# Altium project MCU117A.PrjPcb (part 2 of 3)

## Sheet MCU117A_EtherCAT.SchDoc
size 431 x 279 mm; Date: Not shown in title block; ApprovedBy: Not shown in title block; CheckedBy: Not shown in title block; Author: Not shown in title block; CompanyName: Not shown in title block; Engineer: Not shown in title block; Organization: Not shown in title block; Address1: Not shown in title block; Address2: Not shown in title block; Address3: Not shown in title block; Address4: Not shown in title block; DocumentNumber: 6; Revision: Use project parameter SCH_Rev; SheetNumber: 6; SheetTotal: 9; PageSetup: Record=PageOptions¦CenterHorizontal=True¦CenterVertical=True¦PrintScale=1.00¦XCorrection=1.00¦YCorrection=1.00¦PrintKind=0¦BorderSize=5000000¦LeftOffset=0¦BottomOffset=0¦Orientation=2¦PaperLength=1000¦PaperWidth=1000¦Scale=100¦PaperSource=15¦PrintQuality=600¦MediaType=1¦DitherType=10¦PaperKind=Letter¦PrintScaleMode=1
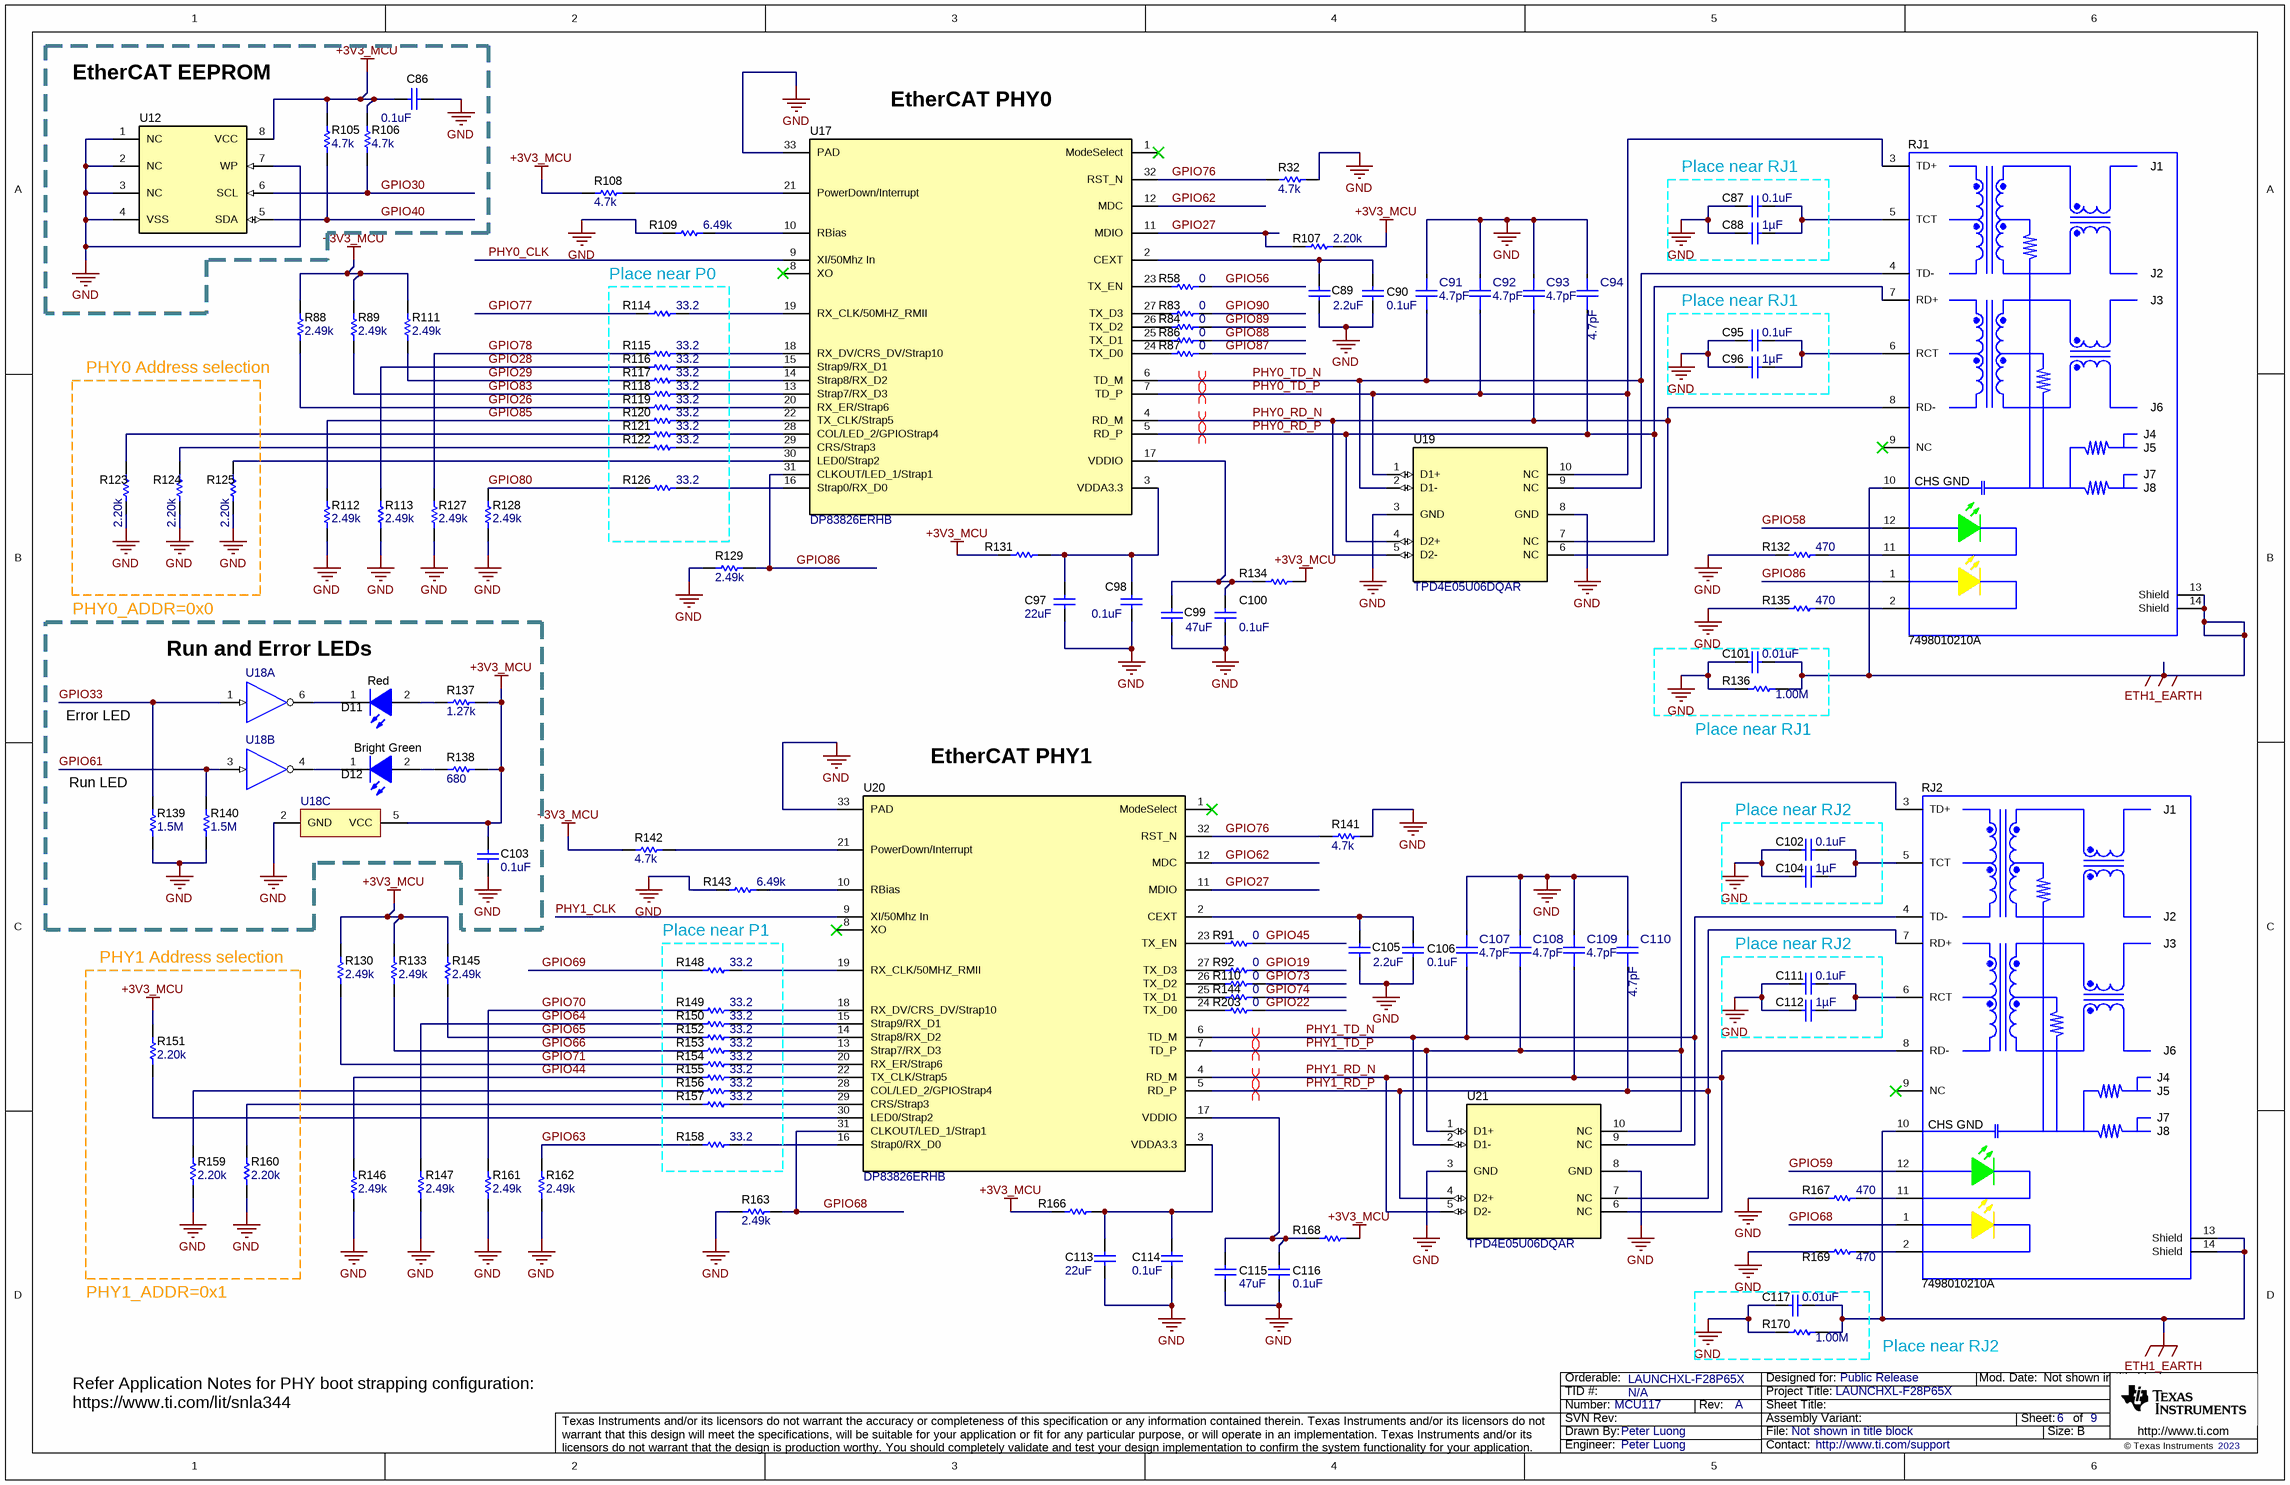
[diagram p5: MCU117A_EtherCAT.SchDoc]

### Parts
C86  ValueDisplayed: 0.1uF  [0402]  (hidden comment: 885012205037)
C87  ValueDisplayed: 0.1uF  [0402]  (hidden comment: CGA2B3X7R1H104K050BB)
C88  ValueDisplayed: 1µF  [0402]  (hidden comment: GRM155R61E105KE11D)
C89  ValueDisplayed: 2.2uF  [0402_065]  (hidden comment: C1005X5R1V225K050BC)
C90  ValueDisplayed: 0.1uF  [0402]  (hidden comment: 885012205037)
C91  ValueDisplayed: 4.7pF  [FP-885012005053_0402-MFG]  (hidden comment: 885012005053)
C92  ValueDisplayed: 4.7pF  [FP-885012005053_0402-MFG]  (hidden comment: 885012005053)
C93  ValueDisplayed: 4.7pF  [FP-885012005053_0402-MFG]  (hidden comment: 885012005053)
C94  ValueDisplayed: 4.7pF  [FP-885012005053_0402-MFG]  (hidden comment: 885012005053)
C95  ValueDisplayed: 0.1uF  [0402]  (hidden comment: CGA2B3X7R1H104K050BB)
C96  ValueDisplayed: 1µF  [0402]  (hidden comment: GRM155R61E105KE11D)
C97  ValueDisplayed: 22uF  [0603]  (hidden comment: GRM188R61A226ME15D)
C98  ValueDisplayed: 0.1uF  [0402]  (hidden comment: 885012205037)
C99  ValueDisplayed: 47uF  [0603]  (hidden comment: GRM188R60J476ME15D)
C100  ValueDisplayed: 0.1uF  [0402]  (hidden comment: 885012205037)
C101  ValueDisplayed: 0.01uF  [0402]  (hidden comment: GRM155R71H103KA88D)
C102  ValueDisplayed: 0.1uF  [0402]  (hidden comment: CGA2B3X7R1H104K050BB)
C103  ValueDisplayed: 0.1uF  [0402]  (hidden comment: 885012205037)
C104  ValueDisplayed: 1µF  [0402]  (hidden comment: GRM155R61E105KE11D)
C105  ValueDisplayed: 2.2uF  [0402_065]  (hidden comment: C1005X5R1V225K050BC)
C106  ValueDisplayed: 0.1uF  [0402]  (hidden comment: 885012205037)
C107  ValueDisplayed: 4.7pF  [FP-885012005053_0402-MFG]  (hidden comment: 885012005053)
C108  ValueDisplayed: 4.7pF  [FP-885012005053_0402-MFG]  (hidden comment: 885012005053)
C109  ValueDisplayed: 4.7pF  [FP-885012005053_0402-MFG]  (hidden comment: 885012005053)
C110  ValueDisplayed: 4.7pF  [FP-885012005053_0402-MFG]  (hidden comment: 885012005053)
C111  ValueDisplayed: 0.1uF  [0402]  (hidden comment: CGA2B3X7R1H104K050BB)
C112  ValueDisplayed: 1µF  [0402]  (hidden comment: GRM155R61E105KE11D)
C113  ValueDisplayed: 22uF  [0603]  (hidden comment: GRM188R61A226ME15D)
C114  ValueDisplayed: 0.1uF  [0402]  (hidden comment: 885012205037)
C115  ValueDisplayed: 47uF  [0603]  (hidden comment: GRM188R60J476ME15D)
C116  ValueDisplayed: 0.1uF  [0402]  (hidden comment: 885012205037)
C117  ValueDisplayed: 0.01uF  [0402]  (hidden comment: GRM155R71H103KA88D)
D11  value Red  [WL-SMCW_RED_0805]  (hidden comment: 150080SS75000)
D12  value Bright Green  [WL-SMCW_Green_0805]  (hidden comment: 150080VS75000)
R32  ValueDisplayed: 4.7k  [0402]  (hidden comment: CRCW04024K70JNED)
R58  ValueDisplayed: 0  [0402]  (hidden comment: CRCW04020000Z0EDHP)
R83  ValueDisplayed: 0  [0402]  (hidden comment: CRCW04020000Z0EDHP)
R84  ValueDisplayed: 0  [0402]  (hidden comment: CRCW04020000Z0EDHP)
R86  ValueDisplayed: 0  [0402]  (hidden comment: CRCW04020000Z0EDHP)
R87  ValueDisplayed: 0  [0402]  (hidden comment: CRCW04020000Z0EDHP)
R88  ValueDisplayed: 2.49k  [0402]  (hidden comment: CRCW04022K49FKED)
R89  ValueDisplayed: 2.49k  [0402]  (hidden comment: CRCW04022K49FKED)
R91  ValueDisplayed: 0  [0402]  (hidden comment: CRCW04020000Z0EDHP)
R92  ValueDisplayed: 0  [0402]  (hidden comment: CRCW04020000Z0EDHP)
R105  ValueDisplayed: 4.7k  [0402]  (hidden comment: CRCW04024K70JNED)
R106  ValueDisplayed: 4.7k  [0402]  (hidden comment: CRCW04024K70JNED)
R107  ValueDisplayed: 2.20k  [0402]  (hidden comment: CRCW04022K20FKED)
R108  ValueDisplayed: 4.7k  [0402]  (hidden comment: CRCW04024K70JNED)
R109  ValueDisplayed: 6.49k  [0402]  (hidden comment: CRCW04026K49FKED)
R110  ValueDisplayed: 0  [0402]  (hidden comment: CRCW04020000Z0EDHP)
R111  ValueDisplayed: 2.49k  [0402]  (hidden comment: CRCW04022K49FKED)
R112  ValueDisplayed: 2.49k  [0402]  (hidden comment: CRCW04022K49FKED)
R113  ValueDisplayed: 2.49k  [0402]  (hidden comment: CRCW04022K49FKED)
R114  ValueDisplayed: 33.2  [0402]  (hidden comment: CRCW040233R2FKED)
R115  ValueDisplayed: 33.2  [0402]  (hidden comment: CRCW040233R2FKED)
R116  ValueDisplayed: 33.2  [0402]  (hidden comment: CRCW040233R2FKED)
R117  ValueDisplayed: 33.2  [0402]  (hidden comment: CRCW040233R2FKED)
R118  ValueDisplayed: 33.2  [0402]  (hidden comment: CRCW040233R2FKED)
R119  ValueDisplayed: 33.2  [0402]  (hidden comment: CRCW040233R2FKED)
R120  ValueDisplayed: 33.2  [0402]  (hidden comment: CRCW040233R2FKED)
R121  ValueDisplayed: 33.2  [0402]  (hidden comment: CRCW040233R2FKED)
R122  ValueDisplayed: 33.2  [0402]  (hidden comment: CRCW040233R2FKED)
R123  ValueDisplayed: 2.20k  [0402]  (hidden comment: CRCW04022K20FKED)
R124  ValueDisplayed: 2.20k  [0402]  (hidden comment: CRCW04022K20FKED)
R125  ValueDisplayed: 2.20k  [0402]  (hidden comment: CRCW04022K20FKED)
R126  ValueDisplayed: 33.2  [0402]  (hidden comment: CRCW040233R2FKED)
R127  ValueDisplayed: 2.49k  [0402]  (hidden comment: CRCW04022K49FKED)
R128  ValueDisplayed: 2.49k  [0402]  (hidden comment: CRCW04022K49FKED)
R129  ValueDisplayed: 2.49k  [0402]  (hidden comment: CRCW04022K49FKED)
R130  ValueDisplayed: 2.49k  [0402]  (hidden comment: CRCW04022K49FKED)
R131  RMCF0402ZT0R00  [FP-RMCF0402ZT0R00_0402 (1005 metric)-0]  (value not drawn)
R132  ValueDisplayed: 470  [0603]  (hidden comment: CRCW0603470RJNEA)
R133  ValueDisplayed: 2.49k  [0402]  (hidden comment: CRCW04022K49FKED)
R134  RMCF0402ZT0R00  [FP-RMCF0402ZT0R00_0402 (1005 metric)-0]  (value not drawn)
R135  ValueDisplayed: 470  [0603]  (hidden comment: CRCW0603470RJNEA)
R136  ValueDisplayed: 1.00M  [0402]  (hidden comment: RMCF0402FT1M00)
R137  ValueDisplayed: 1.27k  [0402]  (hidden comment: CRCW04021K27FKED)
R138  ValueDisplayed: 680  [0402]  (hidden comment: CRCW0402680RJNED)
R139  ValueDisplayed: 1.5M  [0402]  (hidden comment: CRCW04021M50JNED)
R140  ValueDisplayed: 1.5M  [0402]  (hidden comment: CRCW04021M50JNED)
R141  ValueDisplayed: 4.7k  [0402]  (hidden comment: CRCW04024K70JNED)
R142  ValueDisplayed: 4.7k  [0402]  (hidden comment: CRCW04024K70JNED)
R143  ValueDisplayed: 6.49k  [0402]  (hidden comment: CRCW04026K49FKED)
R144  ValueDisplayed: 0  [0402]  (hidden comment: CRCW04020000Z0EDHP)
R145  ValueDisplayed: 2.49k  [0402]  (hidden comment: CRCW04022K49FKED)
R146  ValueDisplayed: 2.49k  [0402]  (hidden comment: CRCW04022K49FKED)
R147  ValueDisplayed: 2.49k  [0402]  (hidden comment: CRCW04022K49FKED)
R148  ValueDisplayed: 33.2  [0402]  (hidden comment: CRCW040233R2FKED)
R149  ValueDisplayed: 33.2  [0402]  (hidden comment: CRCW040233R2FKED)
R150  ValueDisplayed: 33.2  [0402]  (hidden comment: CRCW040233R2FKED)
R151  ValueDisplayed: 2.20k  [0402]  (hidden comment: CRCW04022K20FKED)
R152  ValueDisplayed: 33.2  [0402]  (hidden comment: CRCW040233R2FKED)
R153  ValueDisplayed: 33.2  [0402]  (hidden comment: CRCW040233R2FKED)
R154  ValueDisplayed: 33.2  [0402]  (hidden comment: CRCW040233R2FKED)
R155  ValueDisplayed: 33.2  [0402]  (hidden comment: CRCW040233R2FKED)
R156  ValueDisplayed: 33.2  [0402]  (hidden comment: CRCW040233R2FKED)
R157  ValueDisplayed: 33.2  [0402]  (hidden comment: CRCW040233R2FKED)
R158  ValueDisplayed: 33.2  [0402]  (hidden comment: CRCW040233R2FKED)
R159  ValueDisplayed: 2.20k  [0402]  (hidden comment: CRCW04022K20FKED)
R160  ValueDisplayed: 2.20k  [0402]  (hidden comment: CRCW04022K20FKED)
R161  ValueDisplayed: 2.49k  [0402]  (hidden comment: CRCW04022K49FKED)
R162  ValueDisplayed: 2.49k  [0402]  (hidden comment: CRCW04022K49FKED)
R163  ValueDisplayed: 2.49k  [0402]  (hidden comment: CRCW04022K49FKED)
R166  RMCF0402ZT0R00  [FP-RMCF0402ZT0R00_0402 (1005 metric)-0]  (value not drawn)
R167  ValueDisplayed: 470  [0603]  (hidden comment: CRCW0603470RJNEA)
R168  RMCF0402ZT0R00  [FP-RMCF0402ZT0R00_0402 (1005 metric)-0]  (value not drawn)
R169  ValueDisplayed: 470  [0603]  (hidden comment: CRCW0603470RJNEA)
R170  ValueDisplayed: 1.00M  [0402]  (hidden comment: RMCF0402FT1M00)
R203  ValueDisplayed: 0  [0402]  (hidden comment: CRCW04020000Z0EDHP)
RJ1  7498010210A  [Wurth_7498010210A]
RJ2  7498010210A  [Wurth_7498010210A]
U12  CAT24C16WI-GT3  [SOIC-8]  (value not drawn)
U17  DP83826ERHB  [RHB0032M]
U18  SN74LVC2G06DBVR  [DBV0006A_N]  (value not drawn)  (parts A,B,C of 3)
U19  TPD4E05U06DQAR  [DQA0010A]
U20  DP83826ERHB  [RHB0032M]
U21  TPD4E05U06DQAR  [DQA0010A]

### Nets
+3V3_MCU: C86.2 C103.1 R88.2 R89.2 R105.2 R106.2 R107.2 R108.2 R111.2 R130.2 R131.1 R133.2 R134.2 R137.2 R138.1 R142.2 R145.2 R151.2 R166.1 R168.2 U12.8(VCC) U18.5(VCC)
ETH1_EARTH: C101.2 C117.2 R136.2 R170.2 RJ1.10(CHS_GND) RJ1.13(Shield) RJ1.14(Shield) RJ2.10(CHS_GND) RJ2.13(Shield) RJ2.14(Shield)
GND: C86.1 C87.1 C88.1 C89.2 C90.2 C91.2 C92.2 C93.2 C94.2 C95.1 C96.1 C97.2 C98.2 C99.2 C100.2 C101.1 C102.1 C103.2 C104.1 C105.2 C106.2 C107.2 C108.2 C109.2 C110.2 C111.1 C112.1 C113.2 C114.1 C115.2 C116.1 C117.1 R32.1 R109.1 R112.1 R113.1 R123.1 R124.1 R125.1 R127.1 R128.1 R129.1 R132.1 R135.1 R136.1 R139.2 R140.2 R141.1 R143.1 R146.1 R147.1 R159.1 R160.1 R161.1 R162.1 R163.2 R167.1 R169.1 R170.1 U12.1(NC) U12.2(NC) U12.3(NC) U12.4(VSS) U12.7(WP) U17.33(PAD) U18.2(GND) U19.3(GND) U19.8(GND) U20.33(PAD) U21.3(GND) U21.8(GND)
GPIO19: R92.2
GPIO22: R203.2
GPIO26: R88.1 R119.1
GPIO27: R107.1 U17.11(MDIO) U20.11(MDIO)
GPIO28: R113.2 R116.1
GPIO29: R111.1 R117.1
GPIO30: R106.1 U12.6(SCL)
GPIO33: R139.1 U18.1(1A)
GPIO40: R105.1 U12.5(SDA)
GPIO44: R146.2 R155.1
GPIO45: R91.2
GPIO56: R58.2
GPIO58: RJ1.12(LEFT_LED_ANODE)
GPIO59: RJ2.12(LEFT_LED_ANODE)
GPIO61: R140.1 U18.3(2A)
GPIO62: U17.12(MDC) U20.12(MDC)
GPIO63: R158.1 R162.2
GPIO64: R147.2 R150.1
GPIO65: R145.1 R152.1
GPIO66: R133.1 R153.1
GPIO68: R163.1 RJ2.1(RIGHT_LED_ANODE) U20.31(CLKOUT/LED_1/Strap1)
GPIO69: R148.1
GPIO70: R149.1 R161.2
GPIO71: R130.1 R154.1
GPIO73: R110.2
GPIO74: R144.2
GPIO76: R32.2 R141.2 U17.32(RST_N) U20.32(RST_N)
GPIO77: R114.1
GPIO78: R115.1 R127.2
GPIO80: R126.1 R128.2
GPIO83: R89.1 R118.1
GPIO85: R112.2 R120.1
GPIO86: R129.2 RJ1.1(RIGHT_LED_ANODE) U17.31(CLKOUT/LED_1/Strap1)
GPIO87: R87.2
GPIO88: R86.2
GPIO89: R84.2
GPIO90: R83.2
PHY0_CLK: U17.9(XI/50Mhz_In)
PHY0_RD_N: C93.1 RJ1.8(RD-) U17.4(RD_M) U19.5(D2-) U19.6(NC)
PHY0_RD_P: C94.1 RJ1.7(RD+) U17.5(RD_P) U19.4(D2+) U19.7(NC)
PHY0_TD_N: C91.1 RJ1.4(TD-) U17.6(TD_M) U19.2(D1-) U19.9(NC)
PHY0_TD_P: C92.1 RJ1.3(TD+) U17.7(TD_P) U19.1(D1+) U19.10(NC)
PHY1_CLK: U20.9(XI/50Mhz_In)
PHY1_RD_N: C109.1 RJ2.8(RD-) U20.4(RD_M) U21.5(D2-) U21.6(NC)
PHY1_RD_P: C110.1 RJ2.7(RD+) U20.5(RD_P) U21.4(D2+) U21.7(NC)
PHY1_TD_N: C107.1 RJ2.4(TD-) U20.6(TD_M) U21.2(D1-) U21.9(NC)
PHY1_TD_P: C108.1 RJ2.3(TD+) U20.7(TD_P) U21.1(D1+) U21.10(NC)
NetC87_2: C87.2 C88.2 RJ1.5(TCT)
NetC89_1: C89.1 C90.1 U17.2(CEXT)
NetC95_2: C95.2 C96.2 RJ1.6(RCT)
NetC97_1: C97.1 C98.1 R131.2 U17.3(VDDA3.3)
NetC99_1: C99.1 C100.1 R134.1 U17.17(VDDIO)
NetC102_2: C102.2 C104.2 RJ2.5(TCT)
NetC105_1: C105.1 C106.1 U20.2(CEXT)
NetC111_2: C111.2 C112.2 RJ2.6(RCT)
NetC113_1: C113.1 C114.2 R166.2 U20.3(VDDA3.3)
NetC115_1: C115.1 C116.2 R168.1 U20.17(VDDIO)
NetD11_1: D11.1(K) U18.6(1Y)
NetD11_2: D11.2(A) R137.1
NetD12_1: D12.1(K) U18.4(2Y)
NetD12_2: D12.2(A) R138.2
NetR58_1: R58.1 U17.23(TX_EN)
NetR83_1: R83.1 U17.27(TX_D3)
NetR84_1: R84.1 U17.26(TX_D2)
NetR86_1: R86.1 U17.25(TX_D1)
NetR87_1: R87.1 U17.24(TX_D0)
NetR91_1: R91.1 U20.23(TX_EN)
NetR92_1: R92.1 U20.27(TX_D3)
NetR108_1: R108.1 U17.21(PowerDown/Interrupt)
NetR109_2: R109.2 U17.10(RBias)
NetR110_1: R110.1 U20.26(TX_D2)
NetR114_2: R114.2 U17.19(RX_CLK/50MHZ_RMII)
NetR115_2: R115.2 U17.18(RX_DV/CRS_DV/Strap10)
NetR116_2: R116.2 U17.15(Strap9/RX_D1)
NetR117_2: R117.2 U17.14(Strap8/RX_D2)
NetR118_2: R118.2 U17.13(Strap7/RX_D3)
NetR119_2: R119.2 U17.20(RX_ER/Strap6)
NetR120_2: R120.2 U17.22(TX_CLK/Strap5)
NetR121_1: R121.1 R123.2
NetR121_2: R121.2 U17.28(COL/LED_2/GPIOStrap4)
NetR122_1: R122.1 R124.2
NetR122_2: R122.2 U17.29(CRS/Strap3)
NetR125_2: R125.2 U17.30(LED0/Strap2)
NetR126_2: R126.2 U17.16(Strap0/RX_D0)
NetR132_2: R132.2 RJ1.11(LEFT_LED_CATHODE)
NetR135_2: R135.2 RJ1.2(RIGHT_LED_CATHODE)
NetR142_1: R142.1 U20.21(PowerDown/Interrupt)
NetR143_2: R143.2 U20.10(RBias)
NetR144_1: R144.1 U20.25(TX_D1)
NetR148_2: R148.2 U20.19(RX_CLK/50MHZ_RMII)
NetR149_2: R149.2 U20.18(RX_DV/CRS_DV/Strap10)
NetR150_2: R150.2 U20.15(Strap9/RX_D1)
NetR151_1: R151.1 U20.30(LED0/Strap2)
NetR152_2: R152.2 U20.14(Strap8/RX_D2)
NetR153_2: R153.2 U20.13(Strap7/RX_D3)
NetR154_2: R154.2 U20.20(RX_ER/Strap6)
NetR155_2: R155.2 U20.22(TX_CLK/Strap5)
NetR156_1: R156.1 R159.2
NetR156_2: R156.2 U20.28(COL/LED_2/GPIOStrap4)
NetR157_1: R157.1 R160.2
NetR157_2: R157.2 U20.29(CRS/Strap3)
NetR158_2: R158.2 U20.16(Strap0/RX_D0)
NetR167_2: R167.2 RJ2.11(LEFT_LED_CATHODE)
NetR169_2: R169.2 RJ2.2(RIGHT_LED_CATHODE)
NetR203_1: R203.1 U20.24(TX_D0)

Not connected (* = marked no-connect by the designer): RJ1 9(NC)*; RJ2 9(NC)*; U17 1(ModeSelect)* 8(XO)*; U20 1(ModeSelect)* 8(XO)*

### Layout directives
differential pair: PHY0_RD_N, PHY0_RD_P, PHY0_TD_N, PHY0_TD_P, PHY1_RD_N, PHY1_RD_P, PHY1_TD_N, PHY1_TD_P

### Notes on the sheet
- EtherCAT EEPROM
- (near U17) EtherCAT PHY0
- (near C87) Place near RJ1
- Place near P0
- (near C95) Place near RJ1
- (near R88) PHY0 Address selection
- PHY0_ADDR=0x0
- Run and Error LEDs
- Error LED
- (near U20) EtherCAT PHY1
- (near R136) Place near RJ1
- (near R139) Run LED
- (near C102) Place near RJ2
- PHY1 Address selection
- Place near P1
- (near C111) Place near RJ2
- PHY1_ADDR=0x1
- Place near RJ2
- Refer Application Notes for PHY boot strapping configuration: https://www.ti.com/lit/snla344

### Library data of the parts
C86 C90 C98 C100 C103 C106 C114 C116 = CMP-0006228-2: CAP, CERM, 0.1 uF, 16 V, +/- 10%, X7R, 0402; Manufacturer: Wurth Elektronik; TaMin_C: -55°C; Polarized: N; SizeAreaWB_mm2: 3; Value1: Unknown; U/M: EA; Value: 0.1uF; TaMax_C: 125°C; SizeZ_mm: 0.6; SizeX_mm: 1; SizeY_mm: 0.5; Value2: 16V; Cap_F: 100nF; AEC Category: Q200
C87 C95 C102 C111 = CMP-0006325-2: CAP, CERM, 0.1 uF, 50 V, +/- 10%, X7R, AEC-Q200 Grade 1, 0402; Manufacturer: TDK; TaMin_C: -55°C; ESR_ohm: 39.064m; Polarized: N; SizeAreaWB_mm2: 3; Value1: 0.039064 ohm; U/M: EA; Value: 0.1uF; TaMax_C: 125°C; SizeZ_mm: 0.6; SizeX_mm: 1; SizeY_mm: 0.5; Value2: 50V; AEC Qualified: Y; Cap_F: 100nF; IRMS_A: 814.669mA; AEC Category: Q200
C88 C96 C104 C112 = CMP-0086061-1: CAP, CERM, 1 µF, 25 V,+/- 10%, X5R, 0402; Manufacturer: MuRata; SizeY_mm: 0.5; TaMin_C: -55°C; VDC_V: 25V; Polarized: N; AEC Category: Q200; SizeX_mm: 1; SizeAreaWB_mm2: 3; SizeZ_mm: 0.6; Value: 1uF; TaMax_C: 85°C; U/M: EA
C89 C105 = CMP-0006283-2: CAP, CERM, 2.2 uF, 35 V, +/- 10%, X5R, 0402; Manufacturer: TDK; TaMin_C: -55°C; ESR_ohm: 5.925m; Polarized: N; SizeAreaWB_mm2: 3; Value1: 0.005925 ohm; U/M: EA; Value: 2.2uF; TaMax_C: 85°C; SizeZ_mm: 0.65; SizeX_mm: 1; SizeY_mm: 0.5; Value2: 35V; Cap_F: 2.2µF; IRMS_A: 2.0559A; AEC Category: Q200
C91-C94 C107-C110 = CMP-0096999-1: 4.7 pF ±0.5pF 50V Ceramic Capacitor C0G, NP0 0402 (1005 Metric); Manufacturer: Wurth Electronics; Value: 4.7pF; TempCo: 30ppm/°C; SizeZ_mm: 0.55mm; AEC Qualified: No
C97 C113 = CMP-0007324-5: CAP, CERM, 22 uF, 10 V, +/- 20%, X5R, 0603; Manufacturer: MuRata; TaMin_C: -55°C; Polarized: N; SizeAreaWB_mm2: 4.68; Value1: Unknown; U/M: EA; Value: 22uF; TaMax_C: 85°C; SizeZ_mm: 1; SizeX_mm: 1.6; SizeY_mm: 0.8; Value2: 10V; SizeArea_mm2: 1.28; Cap_F: 22µF; AEC Category: Q200
C99 C115 = CMP-0007313-5: CAP, CERM, 47 uF, 6.3 V, +/- 20%, X5R, 0603; Manufacturer: MuRata; TaMin_C: -55°C; Polarized: N; SizeAreaWB_mm2: 4.68; Value1: Unknown; U/M: EA; Value: 47uF; TaMax_C: 85°C; SizeZ_mm: 1; SizeX_mm: 1.6; SizeY_mm: 0.8; Value2: 6.3V; SizeArea_mm2: 1.28; Cap_F: 47µF; AEC Category: Q200
C101 C117 = CMP-0006674-2: CAP, CERM, 0.01 uF, 50 V, +/- 10%, X7R, 0402; Manufacturer: MuRata; TaMin_C: -55°C; Polarized: N; SizeAreaWB_mm2: 3; Value1: Unknown; U/M: EA; Value: 0.01uF; TaMax_C: 125°C; SizeZ_mm: 0.6; SizeX_mm: 1; SizeY_mm: 0.5; Value2: 50V; Cap_F: 10nF; AEC Category: Q200
D11 = CMP-0002951-3: LED, Red, SMD; Manufacturer: Wurth Elektronik; Type: AlInGaP; Vf_V: 1.9V; Io_A: 30mA; Vr_V: 5V; Ir_A: 25µA; Tjmax_C: 85°C; Power_TotalModule: 72mW; Value1: 0.072W; Angle: 140
D12 = CMP-0002960-2: LED, Bright Green, SMD; Manufacturer: Wurth Elektronik; Type: AlInGaP; Vf_V: 2V; Io_A: 20mA; Vr_V: 5V; Tjmax_C: 85°C; Power_TotalModule: 72mW; Value1: 0.072W; Angle: 140; U/M: EA
R32 R105 R106 R108 R141 R142 = CMP-0026938-1: RES, 4.7 k, 5%, 0.063 W, 0402; Manufacturer: Vishay-Dale; Power_W: 63mW; TempCo: 200 ppm/C; Value_Code: 4k70; U/M: EA; Value: 4.7k; EIA_Code: E24; SizeX_mm: 1; SizeY_mm: 0.5; SizeZ_mm: 0.6; Value2: 0.063W; VDC_V: 50V; AEC Category: Q200
R58 R83 R84 R86 R87 R91 R92 R110 R144 R203 = CMP-0081856-1: RES, 0, 0%, 0.2 W, AEC-Q200 Grade 0, 0402; Manufacturer: Vishay-Dale; SizeAreaWB_mm2: 3; SizeArea_mm2: 0.5; AEC Qualified: Y; AEC Category: Q200; Value: 0; SizeZ_mm: 0.6; Power_W: 200mW; VDC_V: 50V; Value2: 0.2W; SizeX_mm: 1
R88 R89 R111-R113 R127-R130 R133 R145-R147 R161-R163 = CMP-0026237-2: RES, 2.49 k, 1%, 0.063 W, AEC-Q200 Grade 0, 0402; Manufacturer: Vishay-Dale; Power_W: 63mW; TempCo: 100 ppm/C; Value_Code: 2k49; Value: 2.49k; EIA_Code: E96; SizeX_mm: 1; SizeY_mm: 0.5; SizeZ_mm: 0.6; Value2: 0.063W; AEC Qualified: Y; VDC_V: 50V; AEC Category: Q200; AEC Grade: 0
R107 R123-R125 R151 R159 R160 = CMP-0026231-2: RES, 2.20 k, 1%, 0.063 W, AEC-Q200 Grade 0, 0402; Manufacturer: Vishay-Dale; Power_W: 63mW; TempCo: 100 ppm/C; Value_Code: 2k20; Value: 2.20k; Res_ohm: 2.2k; SizeX_mm: 1; SizeY_mm: 0.5; SizeZ_mm: 0.6; Value2: 0.063W; AEC Qualified: Y; AEC Category: Q200; AEC Grade: 0
R109 R143 = CMP-0026515-2: RES, 6.49 k, 1%, 0.063 W, AEC-Q200 Grade 0, 0402; Manufacturer: Vishay-Dale; Power_W: 63mW; TempCo: 100 ppm/C; Value_Code: 6k49; Value: 6.49k; EIA_Code: E96; SizeX_mm: 1; SizeY_mm: 0.5; SizeZ_mm: 0.6; Value2: 0.063W; AEC Qualified: Y; VDC_V: 50V; AEC Category: Q200; AEC Grade: 0
R114-R122 R126 R148-R150 R152-R158 = CMP-0026299-2: RES, 33.2, 1%, 0.063 W, AEC-Q200 Grade 0, 0402; Manufacturer: Vishay-Dale; Power_W: 63mW; TempCo: 100 ppm/C; Value_Code: 33R2; Value: 33.2; EIA_Code: E96; SizeX_mm: 1; SizeY_mm: 0.5; SizeZ_mm: 0.6; Value2: 0.063W; AEC Qualified: Y; VDC_V: 50V; AEC Category: Q200; AEC Grade: 0
R131 R134 R166 R168 = CMP-0086542-2: RMCF/RMCP Series General Purpose Thick Film Standard Power and High Power Chip Resistor; Manufacturer: Stackpole
R132 R135 R167 R169 = CMP-0025813-4: RES, 470, 5%, 0.1 W, AEC-Q200 Grade 0, 0603; Manufacturer: Vishay-Dale; Power_W: 100mW; TempCo: 200 ppm/C; Value_Code: 470R; Value: 470; EIA_Code: E24; SizeX_mm: 1.6; SizeY_mm: 0.8; SizeZ_mm: 1; Value2: 0.1W; SizeArea_mm2: 1.28; AEC Qualified: Y; VDC_V: 75V; AEC Category: Q200; AEC Grade: 0
R136 R170 = CMP-0026757-1: RES, 1.00 M, 1%, 0.063 W, AEC-Q200 Grade 0, 0402; Manufacturer: Stackpole Electronics Inc; Power_W: 63mW; TempCo: 100 ppm/C; Value_Code: 1M00; U/M: EA; Value: 1.00Meg; EIA_Code: E96; Res_ohm: 1M; SizeX_mm: 1; SizeY_mm: 0.5; SizeZ_mm: 0.6; Value2: 0.063W; AEC Qualified: Y; VDC_V: 50V; AEC Grade: 0; AEC Category: Q200
R137 = CMP-0026081-3: RES, 1.27 k, 1%, 0.063 W, AEC-Q200 Grade 0, 0402; Manufacturer: Vishay-Dale; Power_W: 63mW; TempCo: 100 ppm/C; Value_Code: 1k27; Value: 1.27k; EIA_Code: E96; SizeX_mm: 1; SizeY_mm: 0.5; SizeZ_mm: 0.6; Value2: 0.063W; AEC Qualified: Y; VDC_V: 50V; AEC Category: Q200; AEC Grade: 0
R138 = CMP-0026962-3: RES, 680, 5%, 0.063 W, AEC-Q200 Grade 0, 0402; Manufacturer: Vishay-Dale; Value: 680; Value_Code: 680R; Power_W: 63mW; Value2: 0.063W; VDC_V: 50V; TempCo: 200 ppm/C; EIA_Code: E24; AEC Category: Q200; AEC Qualified: Y; AEC Grade: 0; SizeArea_mm2: 0.5; SizeX_mm: 1; SizeZ_mm: 0.6
R139 R140 = CMP-0026863-2: RES, 1.5 M, 5%, 0.063 W, AEC-Q200 Grade 0, 0402; Manufacturer: Vishay-Dale; Power_W: 63mW; TempCo: 200 ppm/C; Value_Code: 1M50; Value: 1.5Meg; EIA_Code: E24; SizeX_mm: 1; SizeY_mm: 0.5; SizeZ_mm: 0.6; Value2: 0.063W; AEC Qualified: Y; VDC_V: 50V; AEC Category: Q200; AEC Grade: 0
RJ1 RJ2 = CMP-0086350-1: Connector, RJ45, 1x1, Gold, R/A, SMT; Manufacturer: Wurth Elektronik; Row_Count: 1; Gender: Female
U12 = CMP-0082059-1: 16 Kb I2C EEPROM Serial, SOIC-8; Manufacturer: ON Semiconductor; SizeArea_mm2: 29.351; SizeAreaWB_mm2: 55.131; SizeY_mm: 4.9; SizeZ_mm: 1.75; SizeX_mm: 5.99
U17 U20 = CMP-0860427-2: DP83826ERHB, RHB0032M (VQFN-32); Alternate Manufacturer: Texas Instruments; AEC Category: Q200; SizeArea_mm2: 25; SizeAreaWB_mm2: 49; AEC Qualified: N; CompType: IC; SizeY_mm: 5; SizeZ_mm: 1
U18 = CMP-0051777-2: Dual Inverter Buffer/Driver with Open-Drain Output, DBV0006A, LARGE T&R; Manufacturer: Texas Instruments; Schmitt Trigger: No; Logic: Inverting; F @ Nom Voltage(Max)(Mhz): 150; VCC(Max)(V): 5.5; Rating: Catalog; Sub-Family: Inverting Buffer/Driver; Technology Family: LVC; VCC(Min)(V): 1.65; Voltage(Nom)(V): 1.8,2.5,3.3,5; Output Drive (IOL/IOH)(Max)(mA): 32/-32; Output Type: CMOS; ICC @ Nom Voltage(Max)(mA): 0.01; Bits(#): 2; tpd @ Nom Voltage(Max)(ns): 8.2,4.4,3.9,3.4; Input Type: CMOS/TTL
U19 U21 = CMP-0073613-3: 4-Channel Ultra-Low-Capacitance IEC ESD Protection Diode, DQA0010A (USON-10); Alternate Manufacturer: Texas Instruments; Green_Lifecycle: Active; SizeAreaWB_mm2: 7.0; Green_REACh: Passed; SizeZ_mm: 0.55; SizeX_mm: 1.0; SizeY_mm: 2.5; CompType: IC; AEC Category: Q200; AEC Qualified: N

## Sheet MCU117A_USB_and_Power.SchDoc
size 431 x 279 mm; Date: Not shown in title block; ApprovedBy: Not shown in title block; CheckedBy: Not shown in title block; Author: Not shown in title block; CompanyName: Not shown in title block; Engineer: Not shown in title block; Organization: Not shown in title block; Address1: Not shown in title block; Address2: Not shown in title block; Address3: Not shown in title block; Address4: Not shown in title block; DocumentNumber: 7; Revision: Use project parameter SCH_Rev; SheetNumber: 7; SheetTotal: 9; PageSetup: Record=PageOptions¦CenterHorizontal=True¦CenterVertical=True¦PrintScale=1.00¦XCorrection=1.00¦YCorrection=1.00¦PrintKind=0¦BorderSize=5000000¦LeftOffset=0¦BottomOffset=0¦Orientation=2¦PaperLength=1000¦PaperWidth=1000¦Scale=100¦PaperSource=15¦PrintQuality=600¦MediaType=1¦DitherType=10¦PaperKind=Letter¦PrintScaleMode=1
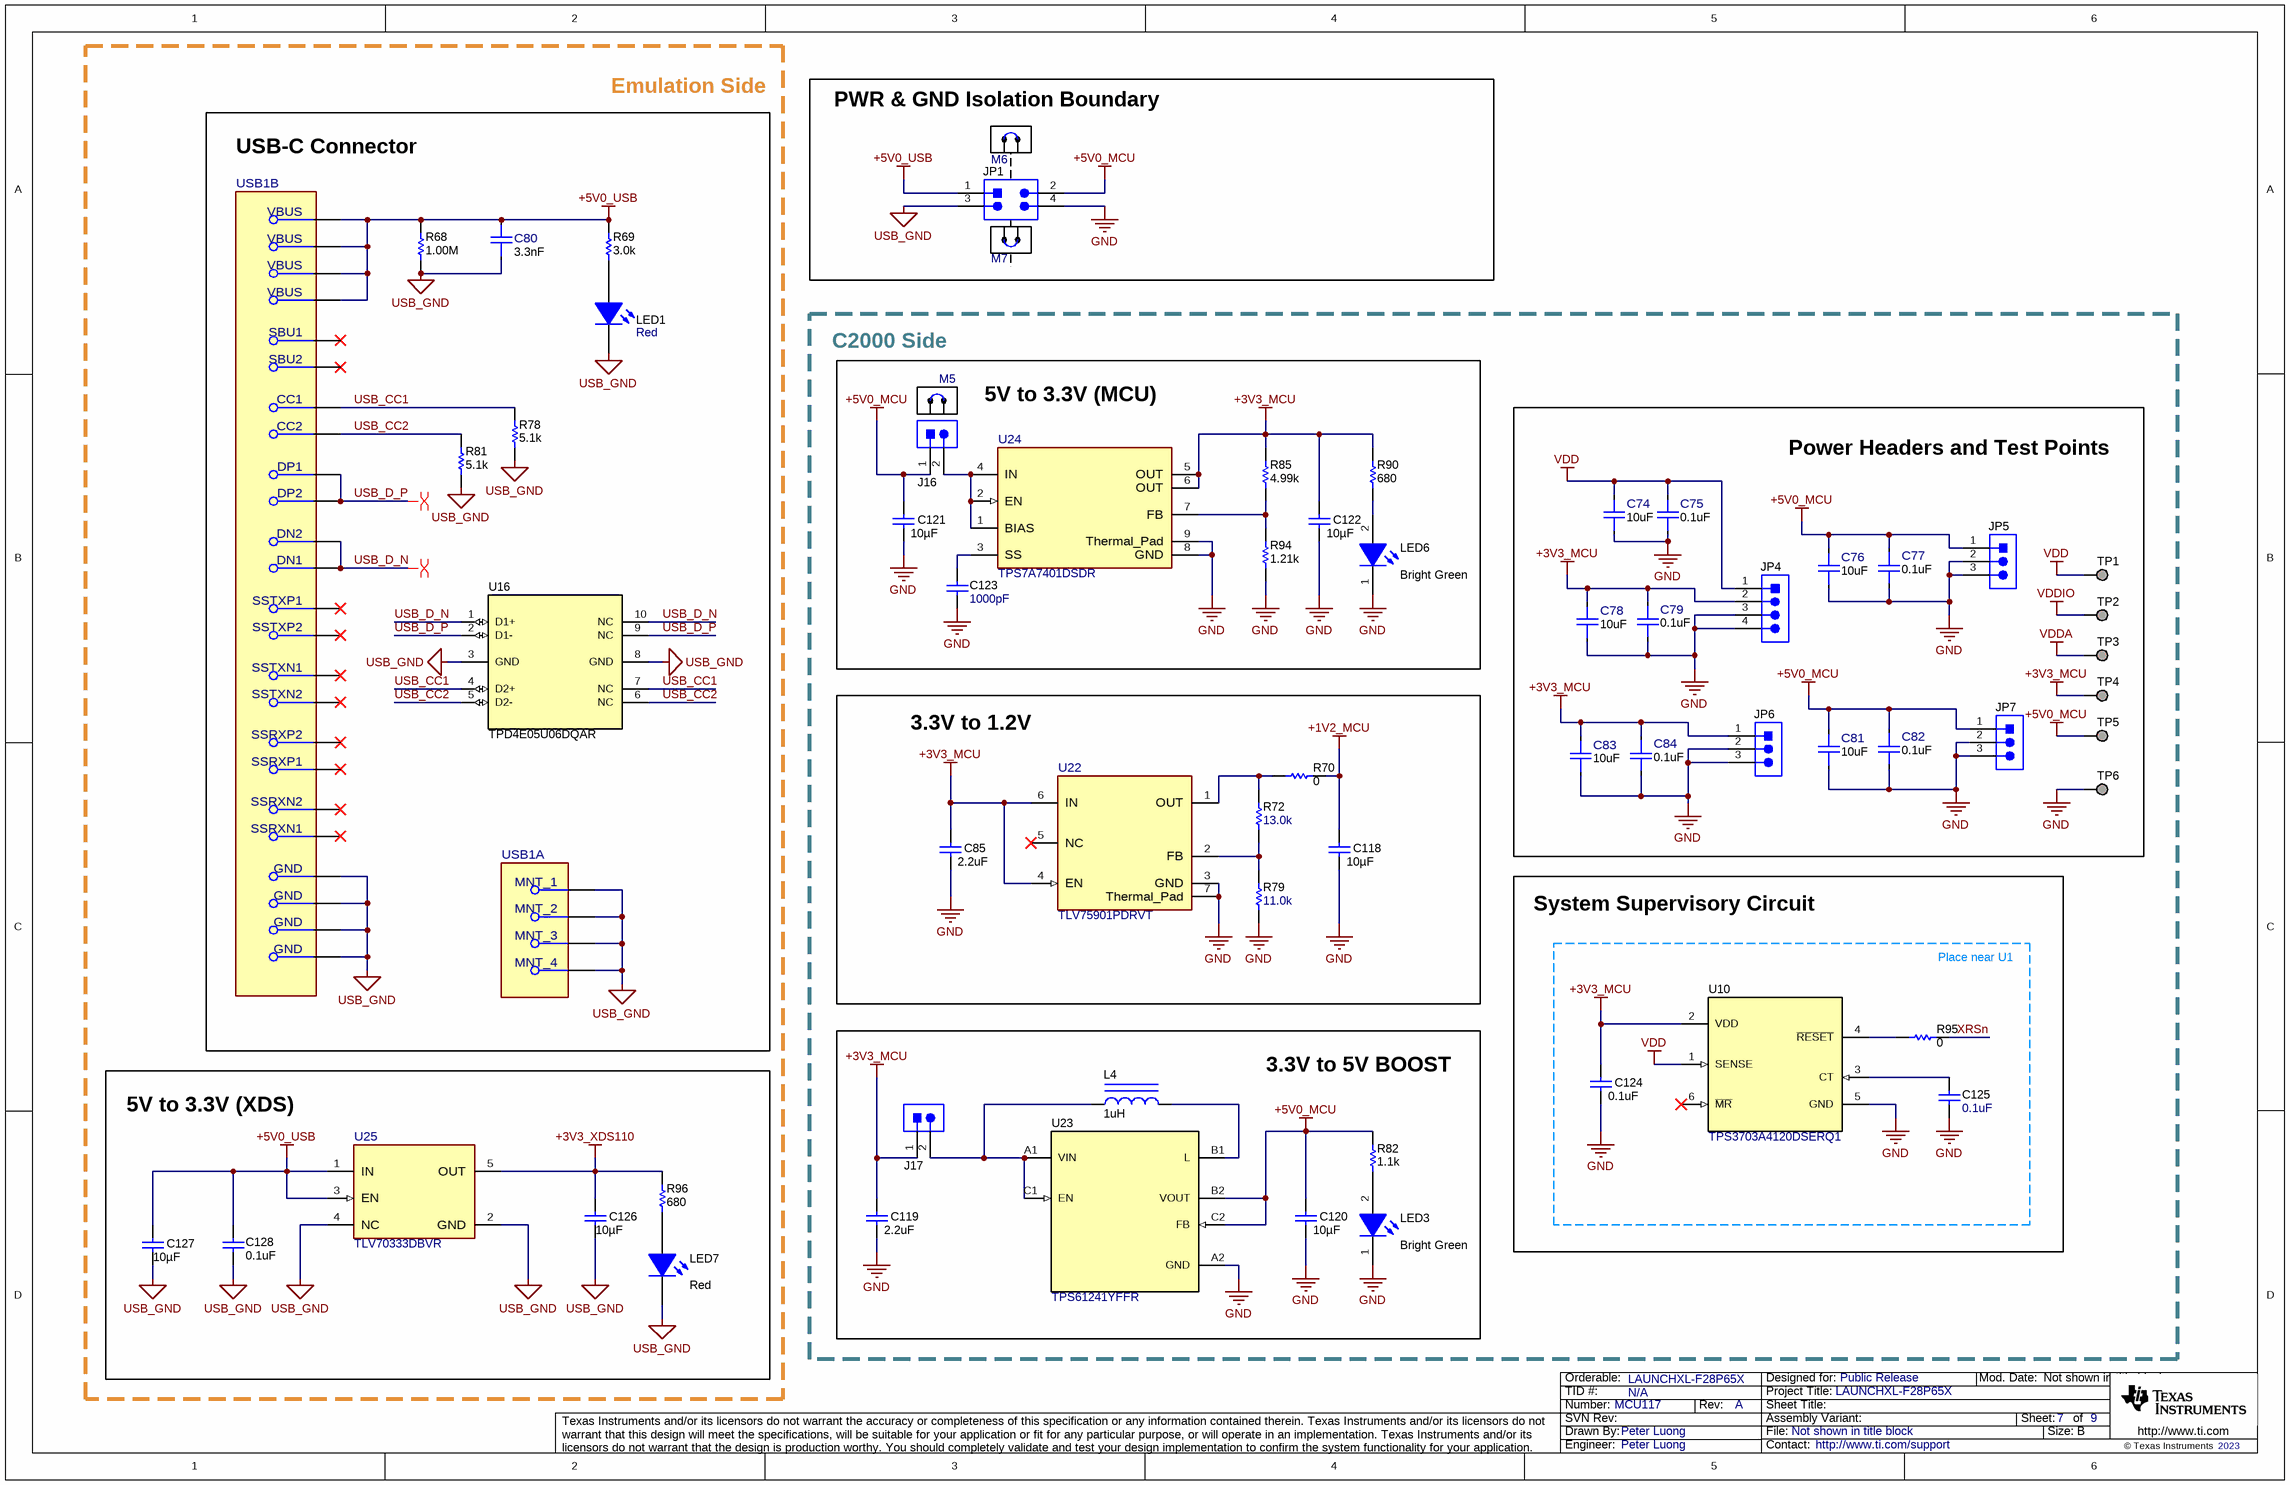
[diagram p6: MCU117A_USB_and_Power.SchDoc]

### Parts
C74  ValueDisplayed: 10uF  [FP-CC0603KRX5R6BB106_0603-MFG]  (hidden comment: CC0603KRX5R6BB106)
C75  ValueDisplayed: 0.1uF  [FP-885012205018_0402-MFG]  (hidden comment: 885012205018)
C76  ValueDisplayed: 10uF  [FP-CC0603KRX5R6BB106_0603-MFG]  (hidden comment: CC0603KRX5R6BB106)
C77  ValueDisplayed: 0.1uF  [FP-885012205018_0402-MFG]  (hidden comment: 885012205018)
C78  ValueDisplayed: 10uF  [FP-CC0603KRX5R6BB106_0603-MFG]  (hidden comment: CC0603KRX5R6BB106)
C79  ValueDisplayed: 0.1uF  [FP-885012205018_0402-MFG]  (hidden comment: 885012205018)
C80  ValueDisplayed: 3.3nF  [FP-885012205064_0402-MFG]  (hidden comment: 885012205064)
C81  ValueDisplayed: 10uF  [FP-CC0603KRX5R6BB106_0603-MFG]  (hidden comment: CC0603KRX5R6BB106)
C82  ValueDisplayed: 0.1uF  [FP-885012205018_0402-MFG]  (hidden comment: 885012205018)
C83  ValueDisplayed: 10uF  [FP-CC0603KRX5R6BB106_0603-MFG]  (hidden comment: CC0603KRX5R6BB106)
C84  ValueDisplayed: 0.1uF  [FP-885012205018_0402-MFG]  (hidden comment: 885012205018)
C85  ValueDisplayed: 2.2uF  [0603]  (hidden comment: 885012106018)
C118  ValueDisplayed: 10µF  [0603]  (hidden comment: GRM188R61C106KAALD)
C119  ValueDisplayed: 2.2uF  [0603]  (hidden comment: 885012106018)
C120  ValueDisplayed: 10µF  [0603]  (hidden comment: GRM188R61C106KAALD)
C121  ValueDisplayed: 10µF  [0603]  (hidden comment: GRM188R61C106KAALD)
C122  ValueDisplayed: 10µF  [0603]  (hidden comment: GRM188R61C106KAALD)
C123  ValueDisplayed: 1000pF  [0402]  (hidden comment: GRM155R61A102KA01D)
C124  ValueDisplayed: 0.1uF  [0402]  (hidden comment: 885012205037)
C125  ValueDisplayed: 0.1uF  [0402]  (hidden comment: 885012205037)
C126  ValueDisplayed: 10µF  [0402_080]  (hidden comment: 0402ZD106MAT2A)
C127  ValueDisplayed: 10µF  [0402_080]  (hidden comment: 0402ZD106MAT2A)
C128  ValueDisplayed: 0.1uF  [0402]  (hidden comment: 885012205037)
J16  61300211121  [WURTH_61300211121]  (value not drawn)
J17  61300211121  [WURTH_61300211121]  (value not drawn)
JP1  TSM-102-01-L-DV  [Samtec_TSM-102-01-x-DV]  (value not drawn)
JP4  61300411121  [WURTH_61300411121]  (value not drawn)
JP5  61300311121  [WURTH_61300311121]  (value not drawn)
JP6  61300311121  [WURTH_61300311121]  (value not drawn)
JP7  61300311121  [WURTH_61300311121]  (value not drawn)
L4  ValueDisplayed: 1uH  [0805_HV]  (hidden comment: LQM21PN1R0MC0D)
LED1  value Red  [WL-SMCW_RED_0805]  (hidden comment: 150080SS75000)
LED3  value Bright Green  [WL-SMCW_Green_0805]  (hidden comment: 150080VS75000)
LED6  value Bright Green  [WL-SMCW_Green_0805]  (hidden comment: 150080VS75000)
LED7  value Red  [WL-SMCW_RED_0805]  (hidden comment: 150080SS75000)
M5  60900213421  [Wurth_60900213421]  (value not drawn)
M6  60900213421  [Wurth_60900213421]  (value not drawn)
M7  60900213421  [Wurth_60900213421]  (value not drawn)
R68  ValueDisplayed: 1.00M  [0402]  (hidden comment: CRCW04021M00FKED)
R69  ValueDisplayed: 3.0k  [0603]  (hidden comment: RC0603JR-073KL)
R70  ValueDisplayed: 0  [0603]  (hidden comment: ERJ-3GEY0R00V)
R72  ValueDisplayed: 13.0k  [0402]  (hidden comment: CRCW040213K0FKED)
R78  ValueDisplayed: 5.1k  [0603]  (hidden comment: RC0603JR-075K1L)
R79  ValueDisplayed: 11.0k  [0402]  (hidden comment: CRCW040211K0FKED)
R81  ValueDisplayed: 5.1k  [0603]  (hidden comment: RC0603JR-075K1L)
R82  ValueDisplayed: 1.1k  [0402]  (hidden comment: CRCW04021K10JNED)
R85  ValueDisplayed: 4.99k  [0402]  (hidden comment: CRCW04024K99FKED)
R90  ValueDisplayed: 680  [0402]  (hidden comment: CRCW0402680RJNED)
R94  ValueDisplayed: 1.21k  [0402]  (hidden comment: CRCW04021K21FKED)
R95  ValueDisplayed: 0  [0603]  (hidden comment: ERJ-3GEY0R00V)
R96  ValueDisplayed: 680  [0402]  (hidden comment: CRCW0402680RJNED)
TP1  TESTPOINT  [TP_50MIL-25MILHOLE]  (value not drawn)  (no BOM)
TP2  TESTPOINT  [TP_50MIL-25MILHOLE]  (value not drawn)  (no BOM)
TP3  TESTPOINT  [TP_50MIL-25MILHOLE]  (value not drawn)  (no BOM)
TP4  TESTPOINT  [TP_50MIL-25MILHOLE]  (value not drawn)  (no BOM)
TP5  TESTPOINT  [TP_50MIL-25MILHOLE]  (value not drawn)  (no BOM)
TP6  TESTPOINT  [TP_50MIL-25MILHOLE]  (value not drawn)  (no BOM)
U10  TPS3703A4120DSERQ1  [DSE0006A]
U16  TPD4E05U06DQAR  [DQA0010A]
U22  TLV75901PDRVT  [DRV0006A-MFG]
U23  TPS61241YFFR  [YFF0006AEAE]
U24  TPS7A7401DSDR  [DSD0008B-MFG]
U25  TLV70333DBVR  [DBV0005A-MFG]
USB1  MUP-U22001  [FP-MUP-U22001_CONN_USB_8MM94_8MM0-MFG]  (value not drawn)  (parts A,B of 2)

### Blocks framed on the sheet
USB-C Connector: C80 LED1 R68 R69 R78 R81 U16 USB1
PWR & GND Isolation Boundary: JP1 M6 M7
5V to 3.3V (MCU): C121-C123 J16 LED6 M5 R85 R90 R94 U24
Power Headers and Test Points: C74-C79 C81-C84 JP4-JP7 TP1-TP6
3.3V to 1.2V: C85 C118 R70 R72 R79 U22
System Supervisory Circuit: C124 C125 R95 U10
5V to 3.3V (XDS): C126-C128 LED7 R96 U25
3.3V to 5V BOOST: C119 C120 J17 L4 LED3 R82 U23

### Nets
+1V2_MCU: C118.1 R70.1
+3V3_MCU: C78.2 C79.1 C83.2 C84.1 C85.1 C119.1 C122.1 C124.1 J17.1 JP4.2 JP6.1 R85.2 R90.1 TP4.1 U10.2(VDD) U22.4(EN) U22.6(IN) U24.5(OUT) U24.6(OUT)
+3V3_XDS110: C126.1 R96.1 U25.5(OUT)
+5V0_MCU: C76.2 C77.1 C81.2 C82.1 C120.1 C121.1 J16.1 JP1.2 JP5.1 JP7.1 R82.2 TP5.1 U23.B2(VOUT) U23.C2(FB)
+5V0_USB: C80.2 C127.1 C128.1 JP1.1 R68.2 R69.2 U25.1(IN) U25.3(EN) USB1.A4(VBUS) USB1.A9(VBUS) USB1.B4(VBUS) USB1.B9(VBUS)
GND: C74.1 C75.1 C76.1 C77.2 C78.1 C79.2 C81.1 C82.2 C83.1 C84.2 C85.2 C118.2 C119.2 C120.2 C121.2 C122.2 C123.2 C124.2 C125.2 JP1.4 JP4.3 JP4.4 JP5.2 JP5.3 JP6.2 JP6.3 JP7.2 JP7.3 LED3.1(K) LED6.1(K) R79.1 R94.1 TP6.1 U10.5(GND) U22.3(GND) U22.7(Thermal_Pad) U23.A2(GND) U24.8(GND) U24.9(Thermal_Pad)
USB_GND: C80.1 C126.2 C127.2 C128.2 JP1.3 LED1.1(K) LED7.1(K) R68.1 R78.1 R81.1 U16.3(GND) U16.8(GND) U25.2(GND) U25.4(NC) USB1.1(MNT_1) USB1.2(MNT_2) USB1.3(MNT_3) USB1.4(MNT_4) USB1.A1(GND) USB1.A12(GND) USB1.B1(GND) USB1.B12(GND)
VDD: C74.2 C75.2 JP4.1 TP1.1 U10.1(SENSE)
VDDA: TP3.1
VDDIO: TP2.1
USB_CC1: R78.2 U16.4(D2+) U16.7(NC) USB1.A5(CC1)
USB_CC2: R81.2 U16.5(D2-) U16.6(NC) USB1.B5(CC2)
USB_D_N: U16.1(D1+) U16.10(NC) USB1.A7(DN1) USB1.B7(DN2)
USB_D_P: U16.2(D1-) U16.9(NC) USB1.A6(DP1) USB1.B6(DP2)
XRSn: R95.1
NetC123_1: C123.1 U24.3(SS)
NetC125_1: C125.1 U10.3(CT)
NetJ16_2: J16.2 U24.1(BIAS) U24.2(EN) U24.4(IN)
NetJ17_2: J17.2 L4.1 U23.A1(VIN) U23.C1(EN)
NetL4_2: L4.2 U23.B1(L)
NetLED1_2: LED1.2(A) R69.1
NetLED3_2: LED3.2(A) R82.1
NetLED6_2: LED6.2(A) R90.2
NetLED7_2: LED7.2(A) R96.2
NetR70_2: R70.2 R72.2 U22.1(OUT)
NetR72_1: R72.1 R79.2 U22.2(FB)
NetR85_1: R85.1 R94.2 U24.7(FB)
NetR95_2: R95.2 U10.4(~{RESET})

Not connected (* = marked no-connect by the designer): U10 6(~{MR})*; U22 5(NC)*; USB1 A2(SSTXP1)* A3(SSTXN1)* A8(SBU1)* A10(SSRXN2)* A11(SSRXP2)* B2(SSTXP2)* B3(SSTXN2)* B8(SBU2)* B10(SSRXN1)* B11(SSRXP1)*

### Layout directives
differential pair: USB_D_N, USB_D_P

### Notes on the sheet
- Emulation Side
- (near M5) C2000 Side
- Place near U1

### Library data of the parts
C74 C76 C78 C81 C83 = CMP-0092309-1: Cap Ceramic 10uF 10V X5R 10% SMD 0603 85C Paper T/R; Manufacturer: YAGEO; Cap_F: 10µF; TempCo: 15%; Category 7542B8484461Ae85: Passive Components; Category 4C11811B7D3097D6: Single Components; SizeZ_mm: 1mm; Category F8883582C9A8234F: Capacitors; AEC Qualified: No; Value: 10µF; Category 85Ce48C4B2B95E09: Uncategorized
C75 C77 C79 C82 C84 = CMP-0090362-1: 0.1µF ±10% 10V Ceramic Capacitor X7R 0402 (1005 Metric); Manufacturer: Wurth Electronics; AEC Qualified: No; Value: 100nF; SizeZ_mm: 0.55mm; TempCo: 15%
C80 = CMP-0092424-1: Cap Cer 3300pF 50V X7R 0402; Manufacturer: Wurth Electronics; TempCo: 15%; AEC Qualified: No; Value: 3.3nF; SizeZ_mm: 0.55mm; Tolerance_%: 10%
C85 C119 = CMP-0006825-5: CAP, CERM, 2.2 uF, 16 V, +/- 20%, X5R, 0603; Manufacturer: Wurth Elektronik; TaMin_C: -55°C; Polarized: N; SizeAreaWB_mm2: 4.68; Value1: Unknown; U/M: EA; Value: 2.2uF; TaMax_C: 85°C; SizeZ_mm: 1; SizeX_mm: 1.6; SizeY_mm: 0.8; Value2: 16V; SizeArea_mm2: 1.28; Cap_F: 2.2µF; AEC Category: Q200
C118 C120-C122 = CMP-0086225-1: CAP, CERM, 10 µF, 16 V,+/- 10%, X5R, 0603; Manufacturer: MuRata; SizeZ_mm: 1; SizeX_mm: 1.6; SizeArea_mm2: 1.28; VDC_V: 16V; U/M: EA; AEC Category: Q200; SizeY_mm: 0.8; Polarized: N; TaMax_C: 85°C; Value: 10uF; SizeAreaWB_mm2: 4.68; TaMin_C: -55°C
C123 = CMP-0006560-2: CAP, CERM, 1000 pF, 10 V, +/- 10%, X5R, 0402; Manufacturer: MuRata; TaMin_C: -55°C; Polarized: N; SizeAreaWB_mm2: 3; Value1: Unknown; U/M: EA; Value: 1000pF; TaMax_C: 85°C; SizeZ_mm: 0.6; SizeX_mm: 1; SizeY_mm: 0.5; Value2: 10V; Cap_F: 1nF; AEC Category: Q200
C124 C125 C128 = CMP-0006228-2: as C86 on sheet MCU117A_EtherCAT
C126 C127 = CMP-0078623-1: CAP, CERM, 10 µF, 10 V,+/- 20%, X5R, 0402; Manufacturer: AVX; SizeAreaWB_mm2: 3; SizeArea_mm2: 0.5; AEC Qualified: N; AEC Category: Q200; Value: 10uF; TaMax_C: 85°C; SizeZ_mm: 0.8; TaMin_C: -55°C; VDC_V: 10V; U/M: EA; SizeX_mm: 1
J16 J17 = CMP-0054794-2: Header, 2.54 mm, 2x1, Gold, TH; Manufacturer: Wurth Elektronik; Shrouded: N; Gender: Male; Green_REACh: Passed; Pitch_mm: 2.54; Green_Lifecycle: Active; Row_Count: 1; Cert_UL: Y
JP1 = CMP-0055559-1: Header, 2.54mm, 2x2, Gold, SMT; Manufacturer: Samtec; CNHeader: TRUE; Shrouded: N; Gender: Male; Cert_CSA: Y; Voltage_V: 475V; Row_Count: 2; Pitch_mm: 2.54; CT: FALSE
JP4 = CMP-0054798-2: Header, 2.54 mm, 4x1, Gold, TH; Manufacturer: Wurth Elektronik; Pitch_mm: 2.54; Gender: Male; Row_Count: 1; Cert_UL: Y; Shrouded: N
JP5-JP7 = CMP-0054796-1: Header, 2.54 mm, 3x1, Gold, TH; Manufacturer: Wurth Elektronik; Green_Lifecycle: Active; Green_REACh: Passed; CNHeader: TRUE; CT: FALSE
L4 = CMP-0058739-1: Inductor, Multilayer, Ferrite, 1 uH, 0.8 A, 0.19 ohm, SMD; Manufacturer: MuRata; Irms: 0.8A @ 40C rise; Green_Lifecycle: Active; SizeAreaWB_mm2: 6.75; DCR_ohm: 1.9d; Green_REACh: Passed; Value: 1uH; Imax_A: 8dA; SizeZ_mm: 1.45; SizeX_mm: 2; SizeY_mm: 1.25; Value2: 0.8A; SizeArea_mm2: 2.5; Ind_H: 1µH; AEC Category: Q200
LED1 LED7 = CMP-0002951-3: as D11 on sheet MCU117A_EtherCAT
LED3 LED6 = CMP-0002960-2: as D12 on sheet MCU117A_EtherCAT
M5-M7 = CMP-0003761-2: Shunt, 2.54mm, Gold, Black; Manufacturer: Wurth Elektronik
R68 = CMP-0026100-2: RES, 1.00 M, 1%, 0.063 W, AEC-Q200 Grade 0, 0402; Manufacturer: Vishay-Dale; Value: 1.00Meg; Res_ohm: 1M; Value_Code: 1M00; Power_W: 63mW; Value2: 0.063W; VDC_V: 50V; TempCo: 100 ppm/C; SizeArea_mm2: 0.5; SizeX_mm: 1; SizeZ_mm: 0.6; EIA_Code: E96; AEC Category: Q200; AEC Qualified: Y; AEC Grade: 0
R69 = CMP-0025921-5: RES, 3.0 k, 5%, 0.1 W, 0603; Manufacturer: Yageo; Power_W: 100mW; TempCo: 100 ppm/C; Value_Code: 3k00; Value: 3.0k; EIA_Code: E24; Res_ohm: 3k; SizeX_mm: 1.6; SizeY_mm: 0.8; SizeZ_mm: 1; Value2: 0.1W; SizeArea_mm2: 1.28; AEC Qualified: N; VDC_V: 75V; AEC Category: Q200; SizeAreaWB_mm2: 4.68
R70 R95 = CMP-0025874-4: RES, 0, 5%, 0.1 W, AEC-Q200 Grade 0, 0603; Manufacturer: Panasonic; Power_W: 100mW; TempCo: 600 ppm/C; Value_Code: 0000; Value: 0; EIA_Code: E24; SizeX_mm: 1.6; SizeY_mm: 0.8; SizeZ_mm: 1; Value2: 0.1W; SizeArea_mm2: 1.28; AEC Qualified: Y; VDC_V: 50V; AEC Category: Q200; SizeAreaWB_mm2: 4.68
R72 = CMP-0026003-3: RES, 13.0 k, 1%, 0.063 W, AEC-Q200 Grade 0, 0402; Manufacturer: Vishay-Dale; Power_W: 63mW; TempCo: 100 ppm/C; Value_Code: 13k0; Value: 13.0k; EIA_Code: E96; Res_ohm: 13k; SizeX_mm: 1; SizeY_mm: 0.5; SizeZ_mm: 0.6; Value2: 0.063W; AEC Qualified: Y; VDC_V: 50V; AEC Category: Q200; AEC Grade: 0
R78 R81 = CMP-0025932-5: RES, 5.1 k, 5%, 0.1 W, 0603; Manufacturer: Yageo; Power_W: 100mW; TempCo: 100 ppm/C; Value_Code: 5k10; Value: 5.1k; EIA_Code: E24; SizeX_mm: 1.6; SizeY_mm: 0.8; SizeZ_mm: 1; Value2: 0.1W; SizeArea_mm2: 1.28; AEC Qualified: N; VDC_V: 75V; AEC Category: Q200; SizeAreaWB_mm2: 4.68
R79 = CMP-0025975-3: RES, 11.0 k, 1%, 0.063 W, AEC-Q200 Grade 0, 0402; Manufacturer: Vishay-Dale; Power_W: 63mW; TempCo: 100 ppm/C; Value_Code: 11k0; Value: 11.0k; EIA_Code: E96; Res_ohm: 11k; SizeX_mm: 1; SizeY_mm: 0.5; SizeZ_mm: 0.6; Value2: 0.063W; AEC Qualified: Y; VDC_V: 50V; AEC Category: Q200; AEC Grade: 0
R82 = CMP-0026853-5: RES, 1.1 k, 5%, 0.063 W, AEC-Q200 Grade 0, 0402; Manufacturer: Vishay-Dale; Power_W: 63mW; TempCo: 200 ppm/C; Value_Code: 1k10; Value: 1.1k; EIA_Code: E24; SizeX_mm: 1; SizeY_mm: 0.5; SizeZ_mm: 0.6; Value2: 0.063W; AEC Qualified: Y; VDC_V: 50V; AEC Category: Q200; AEC Grade: 0
R85 = CMP-0026414-2: RES, 4.99 k, 1%, 0.063 W, AEC-Q200 Grade 0, 0402; Manufacturer: Vishay-Dale; Power_W: 63mW; TempCo: 100 ppm/C; Value_Code: 4k99; Value: 4.99k; EIA_Code: E96; SizeX_mm: 1; SizeY_mm: 0.5; SizeZ_mm: 0.6; Value2: 0.063W; AEC Qualified: Y; VDC_V: 50V; AEC Category: Q200; AEC Grade: 0
R90 R96 = CMP-0026962-3: as R138 on sheet MCU117A_EtherCAT
R94 = CMP-0026079-3: RES, 1.21 k, 1%, 0.063 W, AEC-Q200 Grade 0, 0402; Manufacturer: Vishay-Dale; Power_W: 63mW; TempCo: 100 ppm/C; Value_Code: 1k21; Value: 1.21k; EIA_Code: E96; SizeX_mm: 1; SizeY_mm: 0.5; SizeZ_mm: 0.6; Value2: 0.063W; AEC Qualified: Y; VDC_V: 50V; AEC Category: Q200; AEC Grade: 0
TP1-TP6 = CMP-0078143-3: TEST POINT.  No entry in BOM.
U10 = CMP-0081404-1: Automotive High-Accuracy Window Supervisor With Reset Time Delay and Manual Reset, DSE0006A (WSON-6); Alternate Manufacturer: Texas Instruments; SizeAreaWB_mm2: 6.25; SizeZ_mm: 0.8; SizeX_mm: 1.5; SizeArea_mm2: 2.25; CompType: IC; AEC Qualified: Y; AEC Category: Q200
U16 = CMP-0073613-3: as U19 on sheet MCU117A_EtherCAT
U22 = CMP-0091799-1: Linear Voltage Regulator IC Positive Adjustable 1 Output  1A 6-WSON (2x2); Manufacturer: Texas Instruments; SizeZ_mm: 0.8mm; TJmax_C: +125°C; Dropout Voltage: 161mV; Output Voltage: 0.55-5.5V; Number Of Outputs: 1; Nominal Supply Current: 25uA; Standoff Height: 0mm; Output Type: AdjustableProgrammable; Accuracy Percentage: 0.7%; Max Supply Voltage: 6V; Min Supply Voltage: 1.5V; AEC Qualified: No
U23 = CMP-0067212-2: 5V, 500mA, 4MHz Step-Up DC/DC Converter, YFF0006AEAE (DSBGA-6); Alternate Manufacturer: Texas Instruments; Alternate PartNumber: TPS61241YFFT; AEC Qualified: N; Rating: Catalog; SizeX_mm: 0.856; SizeAreaWB_mm2: 4.190848; SizeY_mm: 1.258; SizeArea_mm2: 1.076848; AEC Category: Q200; CompType: IC; SizeZ_mm: 0.625
U24 = CMP-0093421-2: 1.5-A Low-Dropout Linear Regulator With Programmable Soft-Start; Manufacturer: Texas Instruments; Output Type: AdjustableProgrammable; SizeZ_mm: 0.8mm; Min Supply Voltage: 800mV; Number Of Outputs: 1; CompType: IC; Max Supply Voltage: 5.5V; AEC Qualified: No; AEC Category: Q200; Dropout Voltage: 150mV; Output Voltage: 0.65-3.6V; TJmax_C: +125°C; Accuracy Percentage: 0.5%; Standoff Height: 0mm
U25 = CMP-0091939-1: Linear Voltage Regulator IC Positive Fixed 1 Output 300mA SOT-23-5; Manufacturer: Texas Instruments; SizeZ_mm: 1.45mm; Nominal Supply Current: 35-370uA; TJmax_C: +125°C; Output Voltage: 3.3V; Dropout Voltage: 260mV; Standoff Height: 0mm; Accuracy Percentage: 2%; AEC Qualified: No; Max Supply Voltage: 5.5V; Number Of Outputs: 1; Min Supply Voltage: 2V
USB1 = CMP-0092137-1: Connector, USB Type-C 24 pin Mid Mount dual row Receptacle Surface Mount; Manufacturer: MUP; ContactFinish: Gold,Nickel; Usb Standard: OTHER; AEC Qualified: No; Conn Orientation: Horizontal; Shrouded: true; SizeZ_mm: 2.81mm; Is Female: yes; DUT-Pitch_mm: 0.5mm

## Sheet MCU117A_XDS110_MCU.SchDoc
size 431 x 279 mm; Date: Not shown in title block; ApprovedBy: Not shown in title block; CheckedBy: Not shown in title block; Author: Not shown in title block; CompanyName: Not shown in title block; Engineer: Not shown in title block; Organization: Not shown in title block; Address1: Not shown in title block; Address2: Not shown in title block; Address3: Not shown in title block; Address4: Not shown in title block; DocumentNumber: 8; Revision: Use project parameter SCH_Rev; SheetNumber: 8; SheetTotal: 9; PageSetup: Record=PageOptions¦CenterHorizontal=True¦CenterVertical=True¦PrintScale=1.00¦XCorrection=1.00¦YCorrection=1.00¦PrintKind=0¦BorderSize=5000000¦LeftOffset=0¦BottomOffset=0¦Orientation=2¦PaperLength=1000¦PaperWidth=1000¦Scale=100¦PaperSource=15¦PrintQuality=600¦MediaType=1¦DitherType=10¦PaperKind=Letter¦PrintScaleMode=1
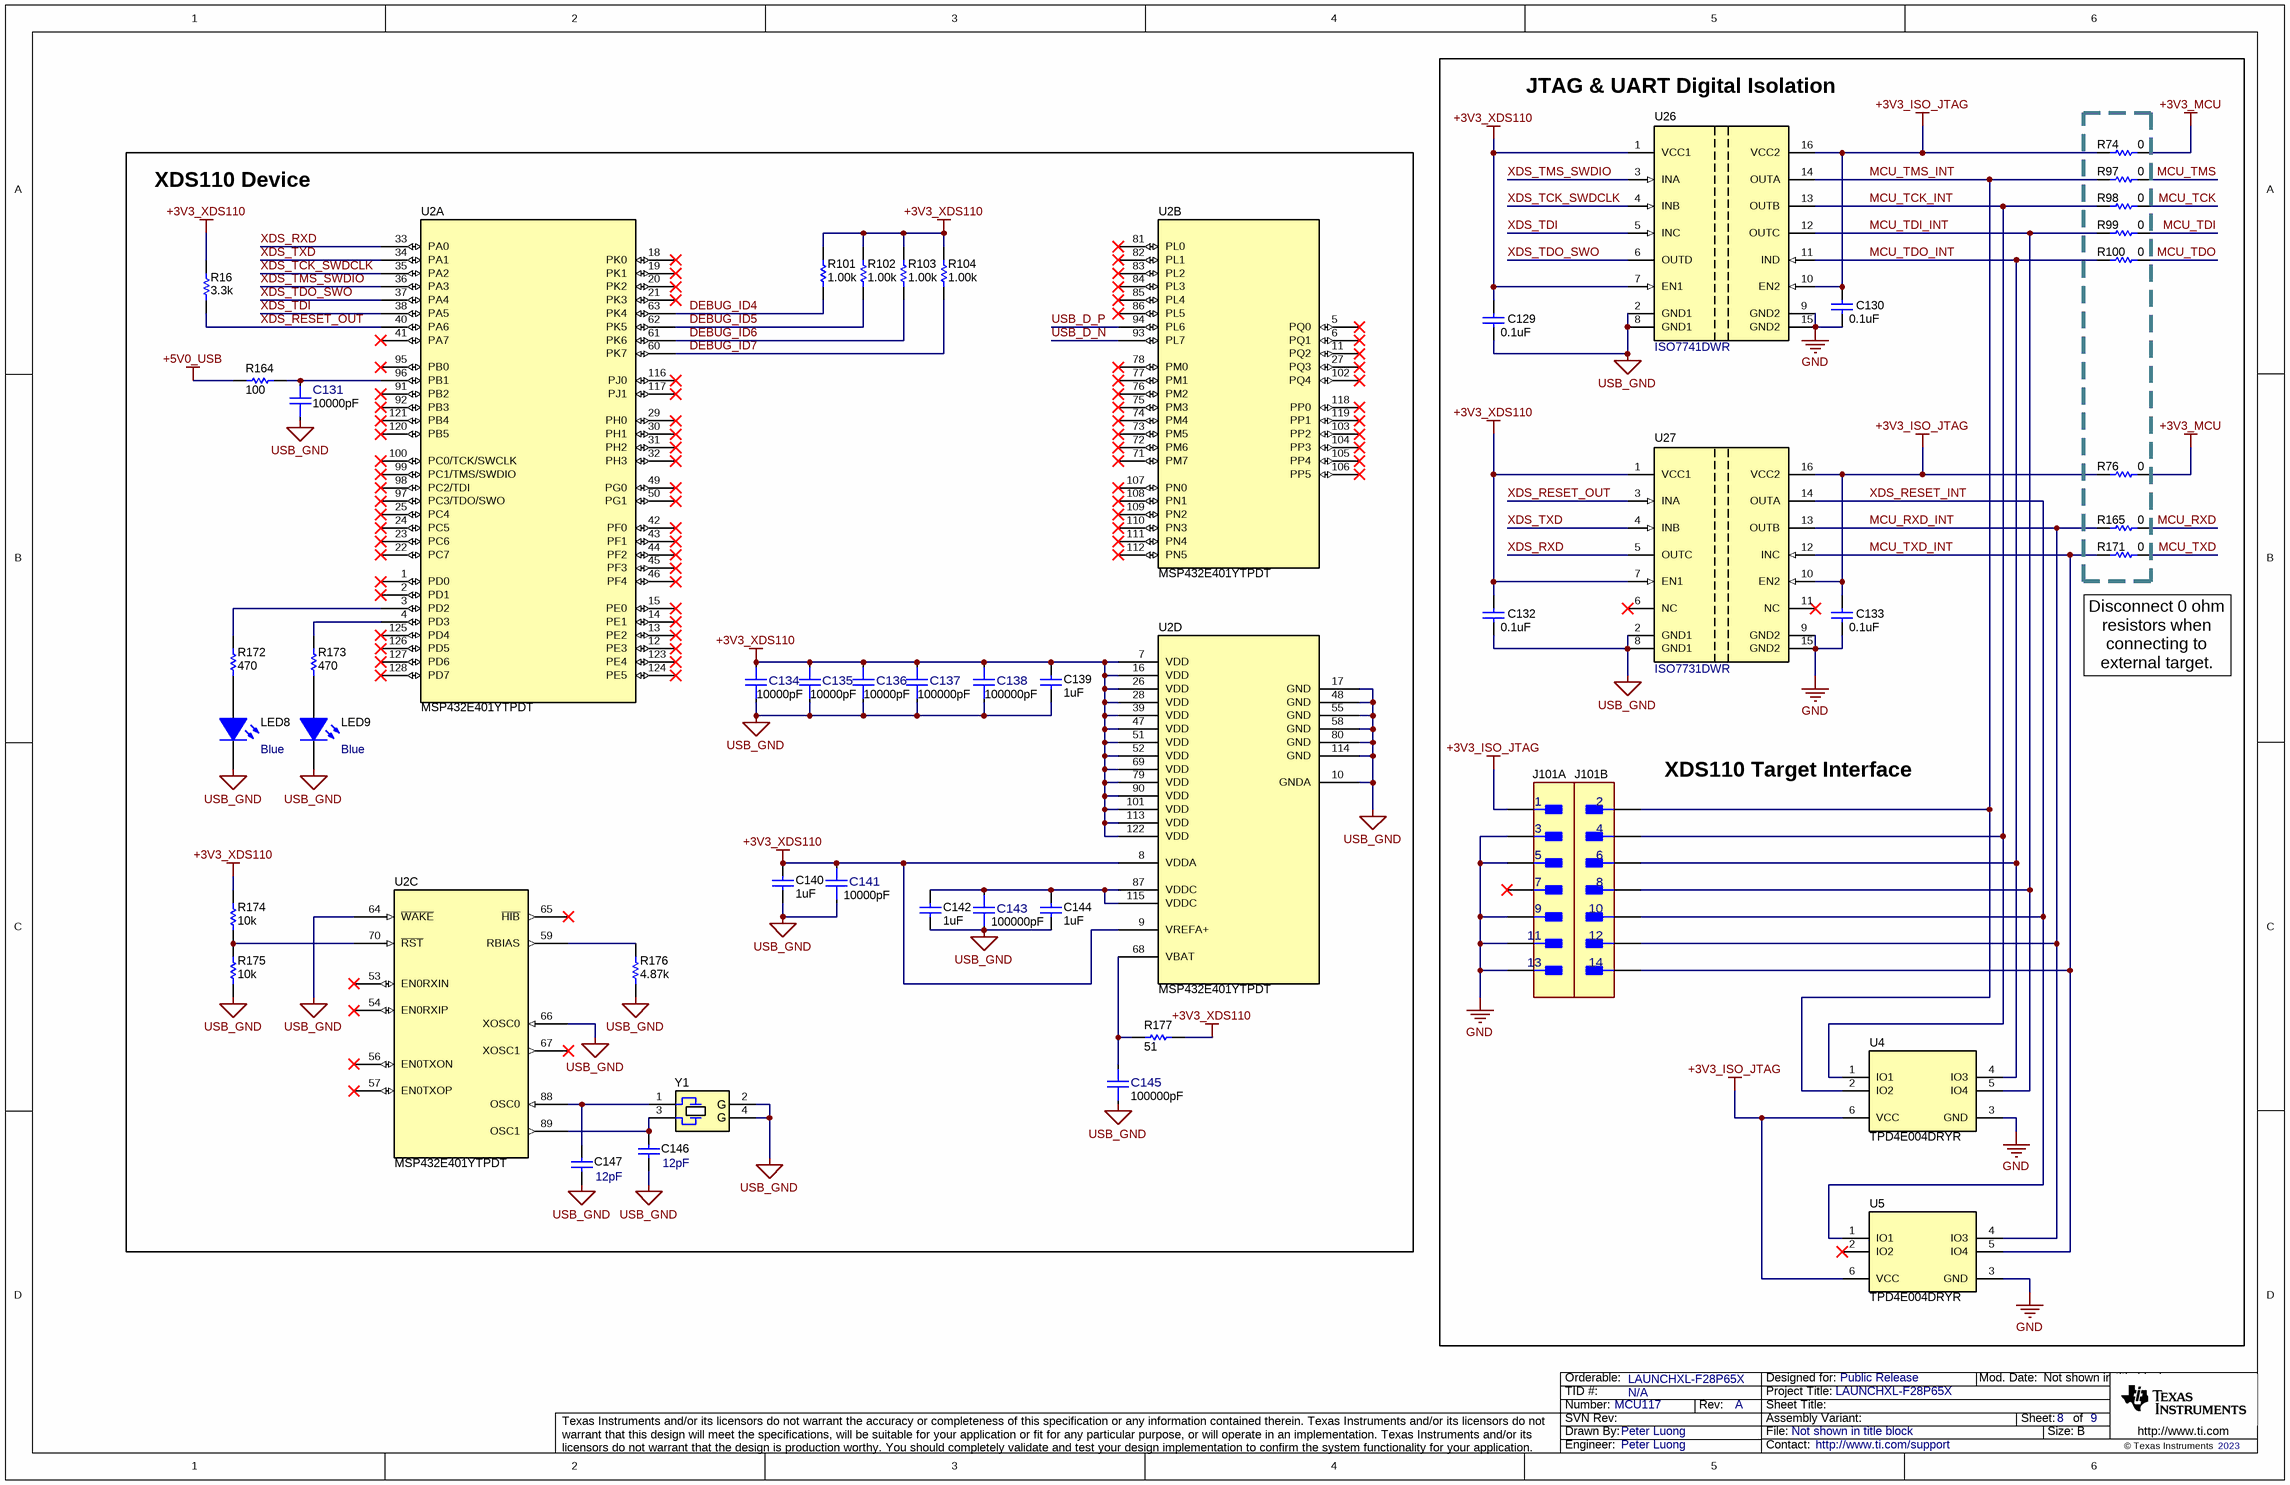
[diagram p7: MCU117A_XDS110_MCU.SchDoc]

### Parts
C129  ValueDisplayed: 0.1uF  [0402]  (hidden comment: 885012205037)
C130  ValueDisplayed: 0.1uF  [0402]  (hidden comment: 885012205037)
C131  ValueDisplayed: 10000pF  [FP-885012205050_0402-MFG]  (hidden comment: 885012205050)
C132  ValueDisplayed: 0.1uF  [0402]  (hidden comment: 885012205037)
C133  ValueDisplayed: 0.1uF  [0402]  (hidden comment: 885012205037)
C134  ValueDisplayed: 10000pF  [FP-885012205050_0402-MFG]  (hidden comment: 885012205050)
C135  ValueDisplayed: 10000pF  [FP-885012205050_0402-MFG]  (hidden comment: 885012205050)
C136  ValueDisplayed: 10000pF  [FP-885012205050_0402-MFG]  (hidden comment: 885012205050)
C137  ValueDisplayed: 100000pF  [FP-885012205018_0402-MFG]  (hidden comment: 885012205018)
C138  ValueDisplayed: 100000pF  [FP-885012205018_0402-MFG]  (hidden comment: 885012205018)
C139  ValueDisplayed: 1uF  [0402]  (hidden comment: 885012105012)
C140  ValueDisplayed: 1uF  [0402]  (hidden comment: 885012105012)
C141  ValueDisplayed: 10000pF  [FP-885012205050_0402-MFG]  (hidden comment: 885012205050)
C142  ValueDisplayed: 1uF  [0402]  (hidden comment: 885012105012)
C143  ValueDisplayed: 100000pF  [FP-885012205018_0402-MFG]  (hidden comment: 885012205018)
C144  ValueDisplayed: 1uF  [0402]  (hidden comment: 885012105012)
C145  ValueDisplayed: 100000pF  [FP-885012205018_0402-MFG]  (hidden comment: 885012205018)
C146  ValueDisplayed: 12pF  [0402]  (hidden comment: CL05C120JB5NNNC)
C147  ValueDisplayed: 12pF  [0402]  (hidden comment: CL05C120JB5NNNC)
J101  FTSH-107-01-F-DV-K  [FP-FTSH-107-01-F-DV-K_HDR14-MFG]  (value not drawn)  (parts A,B of 2)
LED8  value Blue  [LTST-C170TBKT_Blue]  (hidden comment: LTST-C170TBKT)
LED9  value Blue  [LTST-C170TBKT_Blue]  (hidden comment: LTST-C170TBKT)
R16  ValueDisplayed: 3.3k  [0402]  (hidden comment: CRCW04023K30JNED)
R74  ValueDisplayed: 0  [0603]  (hidden comment: ERJ-3GEY0R00V)
R76  ValueDisplayed: 0  [0603]  (hidden comment: ERJ-3GEY0R00V)
R97  ValueDisplayed: 0  [0603]  (hidden comment: ERJ-3GEY0R00V)
R98  ValueDisplayed: 0  [0603]  (hidden comment: ERJ-3GEY0R00V)
R99  ValueDisplayed: 0  [0603]  (hidden comment: ERJ-3GEY0R00V)
R100  ValueDisplayed: 0  [0603]  (hidden comment: ERJ-3GEY0R00V)
R101  ValueDisplayed: 1.00k  [0402]  (hidden comment: CRCW04021K00FKED)
R102  ValueDisplayed: 1.00k  [0402]  (hidden comment: CRCW04021K00FKED)
R103  ValueDisplayed: 1.00k  [0402]  (hidden comment: CRCW04021K00FKED)
R104  ValueDisplayed: 1.00k  [0402]  (hidden comment: CRCW04021K00FKED)
R164  ValueDisplayed: 100  [0402]  (hidden comment: CRCW0402100RJNED)
R165  ValueDisplayed: 0  [0603]  (hidden comment: ERJ-3GEY0R00V)
R171  ValueDisplayed: 0  [0603]  (hidden comment: ERJ-3GEY0R00V)
R172  ValueDisplayed: 470  [0402]  (hidden comment: RC0402FR-07470RL)
R173  ValueDisplayed: 470  [0402]  (hidden comment: RC0402FR-07470RL)
R174  ValueDisplayed: 10k  [0402]  (hidden comment: CRCW040210K0JNED)
R175  ValueDisplayed: 10k  [0402]  (hidden comment: CRCW040210K0JNED)
R176  ValueDisplayed: 4.87k  [0402]  (hidden comment: CRCW04024K87FKED)
R177  ValueDisplayed: 51  [0402]  (hidden comment: CRCW040251R0JNED)
U2  MSP432E401YTPDT  [PDT0128A]  (parts A,B,C,D of 4)
U4  TPD4E004DRYR  [DRY0006A]
U5  TPD4E004DRYR  [DRY0006A]
U26  ISO7741DWR  [DW0016B_HV]
U27  ISO7731DWR  [DW0016B_HV]
Y1  NX3225GA-16.000M-STD-CRG-1  [NDK_NX3225GA]  (value not drawn)

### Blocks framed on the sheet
XDS110 Device: C131 C134-C147 LED8 LED9 R16 R101-R104 R164 R172-R177 U2 Y1

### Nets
+3V3_ISO_JTAG: C130.1 C133.1 J101.1 R74.1 R76.1 U4.6(VCC) U5.6(VCC) U26.10(EN2) U26.16(VCC2) U27.10(EN2) U27.16(VCC2)
+3V3_MCU: R74.2 R76.2
+3V3_XDS110: C129.1 C132.1 C134.2 C135.2 C136.2 C137.2 C138.2 C139.1 C140.1 C141.2 R16.2 R101.2 R102.2 R103.2 R104.2 R174.2 R177.2 U2.7(VDD) U2.8(VDDA) U2.9(VREFA+) U2.16(VDD) U2.26(VDD) U2.28(VDD) U2.39(VDD) U2.47(VDD) U2.51(VDD) U2.52(VDD) U2.69(VDD) U2.79(VDD) U2.90(VDD) U2.101(VDD) U2.113(VDD) U2.122(VDD) U26.1(VCC1) U26.7(EN1) U27.1(VCC1) U27.7(EN1)
+5V0_USB: R164.1
GND: C130.2 C133.2 J101.3 J101.5 J101.9 J101.11 J101.13 U4.3(GND) U5.3(GND) U26.9(GND2) U26.15(GND2) U27.9(GND2) U27.15(GND2)
USB_GND: C129.2 C131.1 C132.2 C134.1 C135.1 C136.1 C137.1 C138.1 C139.2 C140.2 C141.1 C142.2 C143.1 C144.2 C145.1 C146.2 C147.2 LED8.2(K) LED9.2(K) R175.1 R176.1 U2.10(GNDA) U2.17(GND) U2.48(GND) U2.55(GND) U2.58(GND) U2.64(~{WAKE}) U2.66(XOSC0) U2.80(GND) U2.114(GND) U26.2(GND1) U26.8(GND1) U27.2(GND1) U27.8(GND1) Y1.2(GND) Y1.4(GND)
DEBUG_ID4: R101.1 U2.63(PK4)
DEBUG_ID5: R102.1 U2.62(PK5)
DEBUG_ID6: R103.1 U2.61(PK6)
DEBUG_ID7: R104.1 U2.60(PK7)
MCU_RXD: R165.1
MCU_RXD_INT: J101.12 R165.2 U5.4(IO3) U27.13(OUTB)
MCU_TCK: R98.1
MCU_TCK_INT: J101.4 R98.2 U4.1(IO1) U26.13(OUTB)
MCU_TDI: R99.1
MCU_TDI_INT: J101.8 R99.2 U4.5(IO4) U26.12(OUTC)
MCU_TDO: R100.1
MCU_TDO_INT: J101.6 R100.2 U4.4(IO3) U26.11(IND)
MCU_TMS: R97.1
MCU_TMS_INT: J101.2 R97.2 U4.2(IO2) U26.14(OUTA)
MCU_TXD: R171.1
MCU_TXD_INT: J101.14 R171.2 U5.5(IO4) U27.12(INC)
USB_D_N: U2.93(PL7)
USB_D_P: U2.94(PL6)
XDS_RESET_INT: J101.10 U5.1(IO1) U27.14(OUTA)
XDS_RESET_OUT: R16.1 U2.40(PA6) U27.3(INA)
XDS_RXD: U2.33(PA0) U27.5(OUTC)
XDS_TCK_SWDCLK: U2.35(PA2) U26.4(INB)
XDS_TDI: U2.38(PA5) U26.5(INC)
XDS_TDO_SWO: U2.37(PA4) U26.6(OUTD)
XDS_TMS_SWDIO: U2.36(PA3) U26.3(INA)
XDS_TXD: U2.34(PA1) U27.4(INB)
NetC131_2: C131.2 R164.2 U2.96(PB1)
NetC142_1: C142.1 C143.2 C144.1 U2.87(VDDC) U2.115(VDDC)
NetC145_2: C145.2 R177.1 U2.68(VBAT)
NetC146_1: C146.1 U2.89(OSC1) Y1.3
NetC147_1: C147.1 U2.88(OSC0) Y1.1
NetLED8_1: LED8.1(A) R172.1
NetLED9_1: LED9.1(A) R173.1
NetR172_2: R172.2 U2.3(PD2)
NetR173_2: R173.2 U2.4(PD3)
NetR174_1: R174.1 R175.2 U2.70(~{RST})
NetR176_2: R176.2 U2.59(RBIAS)

Not connected (* = marked no-connect by the designer): J101 7*; U2 1(PD0)* 2(PD1)* 5(PQ0)* 6(PQ1)* 11(PQ2)* 12(PE3)* 13(PE2)* 14(PE1)* 15(PE0)* 18(PK0)* 19(PK1)* 20(PK2)* 21(PK3)* 22(PC7)* 23(PC6)* 24(PC5)* 25(PC4)* 27(PQ3)* 29(PH0)* 30(PH1)* 31(PH2)* 32(PH3)* 41(PA7)* 42(PF0)* 43(PF1)* 44(PF2)* 45(PF3)* 46(PF4)* 49(PG0)* 50(PG1)* 53(EN0RXIN)* 54(EN0RXIP)* 56(EN0TXON)* 57(EN0TXOP)* 65(~{HIB})* 67(XOSC1)* 71(PM7)* 72(PM6)* 73(PM5)* 74(PM4)* 75(PM3)* 76(PM2)* 77(PM1)* 78(PM0)* 81(PL0)* 82(PL1)* 83(PL2)* 84(PL3)* 85(PL4)* 86(PL5)* 91(PB2)* 92(PB3)* 95(PB0)* 97(PC3/TDO/SWO)* 98(PC2/TDI)* 99(PC1/TMS/SWDIO)* 100(PC0/TCK/SWCLK)* 102(PQ4)* 103(PP2)* 104(PP3)* 105(PP4)* 106(PP5)* 107(PN0)* 108(PN1)* 109(PN2)* 110(PN3)* 111(PN4)* 112(PN5)* 116(PJ0)* 117(PJ1)* 118(PP0)* 119(PP1)* 120(PB5)* 121(PB4)* 123(PE4)* 124(PE5)* 125(PD4)* 126(PD5)* 127(PD6)* 128(PD7)*; U5 2(IO2)*; U27 6(NC)* 11(NC)*

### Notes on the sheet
- JTAG & UART Digital Isolation
- (near R171) Disconnect 0 ohm resistors when connecting to external target.
- XDS110 Target Interface

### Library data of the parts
C129 C130 C132 C133 = CMP-0006228-2: as C86 on sheet MCU117A_EtherCAT
C131 C134-C136 C141 = CMP-0090363-1: 10000pF ±10% 25V Ceramic Capacitor X7R 0402 (1005 Metric); Manufacturer: Wurth Electronics; SizeZ_mm: 0.55mm; Cap_F: 10nF; AEC Qualified: No; Value: 10nF; TempCo: 15%
C137 C138 C143 C145 = CMP-0090362-1: as C75 on sheet MCU117A_USB_and_Power
C139 C140 C142 C144 = CMP-0064924-2: CAP, CERM, 1 uF, 10 V,+/- 20%, X5R, 0402; Manufacturer: Wurth Elektronik; Polarized: N; Value: 1uF; U/M: EA; Cap_F: 1µF; Value1: Unknown; VDC_V: 10V; TaMin_C: -55°C; TaMax_C: 85°C; SizeArea_mm2: 0.5; SizeAreaWB_mm2: 3; SizeX_mm: 1; SizeZ_mm: 0.6; AEC Category: Q200
C146 C147 = CMP-0006345-2: CAP, CERM, 12 pF, 50 V, +/- 5%, C0G/NP0, 0402; Manufacturer: Samsung Electro-Mechanics; TaMin_C: -55°C; Polarized: N; SizeAreaWB_mm2: 3; Value1: Unknown; U/M: EA; Value: 12pF; TaMax_C: 125°C; SizeZ_mm: 0.6; SizeX_mm: 1; SizeY_mm: 0.5; Value2: 50V; AEC Category: Q200
J101 = CMP-0092335-1: Connector, Header, Dual Row, 14 pin, .05" pitch/row spacing, Male, Shrouded, Keyed, IDC, SMT; Manufacturer: Samtec; Category 0836C53C3D42D3F1: Connectors; Category 75Fab8F04590Ae3D: Connectors and Adapters; ContactFinish: Gold,Nickel; Standoff Height: 0.15mm; Conn Orientation: Vertical; AEC Qualified: No; Category E7012A0Bd22E3Cc6: Headers & Receptacles; SizeZ_mm: 6.38mm; Category A3C16Ecb93907806: Uncategorized; DUT-Pitch_mm: 1.27mm; Current_A: 3.4A; Row_Count: 2
LED8 LED9 = CMP-0002889-2: LED, Blue, SMD; Manufacturer: Lite-On; Type: AlInGaP; Vf_V: 3.3V; Io_A: 20mA; Value1: W
R16 = CMP-0026918-5: RES, 3.3 k, 5%, 0.063 W, AEC-Q200 Grade 0, 0402; Manufacturer: Vishay-Dale; Value: 3.3k; Value_Code: 3k30; Power_W: 63mW; Value2: 0.063W; VDC_V: 50V; TempCo: 200 ppm/C; SizeArea_mm2: 0.5; SizeX_mm: 1; SizeZ_mm: 0.6; EIA_Code: E24; AEC Category: Q200; AEC Qualified: Y; AEC Grade: 0
R74 R76 R97-R100 R165 R171 = CMP-0025874-4: as R70 on sheet MCU117A_USB_and_Power
R101-R104 = CMP-0026071-3: RES, 1.00 k, 1%, 0.063 W, AEC-Q200 Grade 0, 0402; Manufacturer: Vishay-Dale; Power_W: 63mW; TempCo: 100 ppm/C; Value_Code: 1k00; Value: 1.00k; EIA_Code: E96; Res_ohm: 1k; SizeX_mm: 1; SizeY_mm: 0.5; SizeZ_mm: 0.6; Value2: 0.063W; AEC Qualified: Y; VDC_V: 50V; AEC Category: Q200; AEC Grade: 0
R164 = CMP-0026824-3: RES, 100, 5%, 0.063 W, AEC-Q200 Grade 0, 0402; Manufacturer: Vishay-Dale; Value: 100; Value_Code: 100R; Power_W: 63mW; Value2: 0.063W; VDC_V: 50V; TempCo: 200 ppm/C; SizeArea_mm2: 0.5; SizeX_mm: 1; SizeZ_mm: 0.6; EIA_Code: E24; AEC Category: Q200; AEC Qualified: Y; AEC Grade: 0
R172 R173 = CMP-0026736-1: RES, 470, 1%, 0.063 W, 0402; Manufacturer: Yageo America; Power_W: 63mW; TempCo: 100 ppm/C; Value_Code: 470R; U/M: EA; Value: 470; SizeX_mm: 1; SizeY_mm: 0.5; SizeZ_mm: 0.6; Value2: 0.063W; AEC Qualified: N; VDC_V: 50V; AEC Category: Q200
R174 R175 = CMP-0026825-5: RES, 10 k, 5%, 0.063 W, AEC-Q200 Grade 0, 0402; Manufacturer: Vishay-Dale; Value: 10k; Value_Code: 10k0; Power_W: 63mW; Value2: 0.063W; VDC_V: 50V; TempCo: 200 ppm/C; SizeArea_mm2: 0.5; SizeX_mm: 1; SizeZ_mm: 0.6; EIA_Code: E24; AEC Category: Q200; AEC Qualified: Y; AEC Grade: 0
R176 = CMP-0026413-2: RES, 4.87 k, 1%, 0.063 W, AEC-Q200 Grade 0, 0402; Manufacturer: Vishay-Dale; Value: 4.87k; Value_Code: 4k87; Power_W: 63mW; Value2: 0.063W; VDC_V: 50V; TempCo: 100 ppm/C; SizeArea_mm2: 0.5; SizeX_mm: 1; SizeZ_mm: 0.6; EIA_Code: E96; AEC Category: Q200; AEC Qualified: Y; AEC Grade: 0
R177 = CMP-0026946-3: RES, 51, 5%, 0.063 W, AEC-Q200 Grade 0, 0402; Manufacturer: Vishay-Dale; Value: 51; Value_Code: 51R0; Power_W: 63mW; Value2: 0.063W; VDC_V: 50V; TempCo: 200 ppm/C; SizeArea_mm2: 0.5; SizeX_mm: 1; SizeZ_mm: 0.6; EIA_Code: E24; AEC Category: Q200; AEC Qualified: Y; AEC Grade: 0
U2 = CMP-0077953-1: MSP432E401YTPDT, PDT0128A (TQFP-128); Alternate PartNumber: MSP432E401YTPDTR; Alternate Manufacturer: Texas Instruments; SizeAreaWB_mm2: 324; SizeZ_mm: 1.2; SizeX_mm: 16; SizeArea_mm2: 256; CompType: IC; AEC Qualified: N; AEC Category: Q200
U4 U5 = CMP-0043115-3: 4-Channel ESD Protection Array for High-Speed Data Interfaces, DRY0006A (USON-6); Manufacturer: Texas Instruments; IO Leakage Current(nA): 1; USB High Speed: TRUE; IO Capacitance(Typ)(pF): 1.6; Eco-Plan: Green (RoHS & no Sb/Br); IEC 61000-4-2 Contact(+/- kV): 8; Breakdown Voltage(Min)(V): 6; IEC 61000-4-2 Air-Gap(+/- kV): 12; AEC Category: Q200; AEC Qualified: N; CompType: IC; SizeAreaWB_mm2: 4.9; SizeArea_mm2: 1.45; SizeX_mm: 1.0; SizeZ_mm: 0.6; Rating: Catalog
U26 = CMP-0076064-3: High-Speed, Low-Power, Robust EMC Quad-Channel Digital Isolator, DW0016B (SOIC-16); Manufacturer: Texas Instruments; Green_Lifecycle: Active; AEC Category: Q200; CompType: IC; Green_REACh: Passed; SizeAreaWB_mm2: 152.52; SizeX_mm: 10.4; Rating: Catalog; SizeY_mm: 10.3; AEC Qualified: N; SizeZ_mm: 2.65; SizeArea_mm2: 107.12
U27 = CMP-0078446-2: High Speed, Robust EMC Triple-Channel Digital Isolators, DW0016B (SOIC-16); Manufacturer: Texas Instruments; AEC Qualified: N; CompType: IC; Rating: Catalog; SizeArea_mm2: 107.12; SizeX_mm: 10.4; SizeAreaWB_mm2: 152.52; AEC Category: Q200; SizeZ_mm: 2.65; SizeY_mm: 10.3
Y1 = CMP-0004635-3: Crystal, 16 MHz, 8pF, SMD; Manufacturer: NDK; TaMin_C: -10°C; TaMax_C: 70°C; Frequency Stability: +/-30ppm; Frequency_Fixed: 16MHz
